(* Logix 5000 project; controller Test vendor 1 type 14 code 92 rev 33.11; software revision 33.03 *)

TASK MainTask (continuous, watchdog 500 ms) : MainProgram

MODULES
   Local : vendor 1 type 14 code 92 (ICP 0, rev 33.11)
      IN : vendor 1 type 7 code 1 (ICP 3, rev 3.2, Input RPI 20 ms)
      O : vendor 1 type 7 code 15 (ICP 2, rev 3.2, Output RPI 20 ms)
      Ethernet : 1756-ENBT (ICP 1, Ethernet 192.168.0.98, rev 6.4)
         IOLM1 : DXM (Ethernet 192.168.0.1, rev 2.22, StandardDataDriven RPI 20 ms)
END_MODULES

TYPE Banner_IOL_Port_v4 :   // UDT that has all of the data items necessary to communicate with a specific Port on a IO-Link Master
STRUCT
   Port_Controlled : INT;   // Each bit represents a port on an IO-Link Master. Set to 1 to tell AOI to control that port.
   Port_Activate : INT;   // Each bit represents a port on an IO-Link Master. When ON that port will process any commands in queue.
   Port_Read : INT;   // Each bit represents a port on an IO-Link Master. Used to determine when device AOI has requested a Read command.
   Port_Write : INT;   // Each bit represents a port on an IO-Link Master. Used to determine when device AOI has requested a Write command.
   Port_RW_Complete : INT;   // Each bit represents a port on an IO-Link Master. Tells device AOI that Read or Write request has been completed.
   Port_Device_Read : INT;
   Data_Transfer : SINT[190];   // Array to transfer data from IO-Master to device AOIs.
END_STRUCT
END_TYPE

TYPE Banner_IOLM_EL_v4 :   // Error Log for Messages to IOLM.
STRUCT
   RW : SINT;   // 0 = Read, 1 = Write, 3 = AOI Failure.
   Port : SINT;   // Port number that generated error.
   Index : INT;   // IO-Link Index for generated error.
END_STRUCT
END_TYPE

TYPE Banner_IOLM_v4 :   // UDT to control IO-Link Masters.
STRUCT
   Message_Source_Data : SINT[190];
   Message_Destination_Data : SINT[190];
   Error_Log : Banner_IOLM_EL_v4[10];
   Error_Write_Retry : BOOL;
   Num_Error_MSGS : DINT;
   IO_Link_Master_Busy : BOOL;   // 0 = While waiting for a command, 1 = Processing command
   AOI_Reset : BOOL;
   Port_Data : Banner_IOL_Port_v4;   // All of the necessary data to work with the various ports of the IO-Link Master.
   Halt_Operation : BOOL;   // When parameter is 1 the AOI is halted as next available time frame.
   AOI_Halted : BOOL;   // AOI is in standby mode until Halt Operation tag is set back to 0.
END_STRUCT
END_TYPE

TYPE Banner_K50Display_Advanced_PD_V2 :   // K50 Pro Display Advanced
STRUCT
   PDI_Output_Area_1 : SINT;   // 0 = Inactive,1 = Active
   PDI_Output_Area_2 : SINT;   // 0 = Inactive,1 = Active
   PDO_Animation : SINT;   // 0 = Off, 1 = Steady, 2 = Flash, 3 = 2 Color Flash, 4 = 50/50, 5 = 50/50 Rotate, 6 = Chase, 7 = Intensity Sweep, 8 = Color Sweep, 9 Sequence, 10 = Wave, 11 = Double Wave, 12 = Steady Area 1, 13 = Steady Area 2, 14 = Alternate Area1 Area 2
   PDO_Direction : SINT;   // 0 = CCW, 1 = CW
   PDO_Pattern : SINT;   // 0 = Flash, 1 = Strobe, 2 = 3 Pulse, 3 = SOS, 4 = Random
   PDO_Speed : SINT;   // 0 = Slow, 1 = Medium, 2 = Fast, 3 = Custom
   PDO_Dyanamic_Sequence : SINT;   // 0 to 255
   PDO_Sequence_Start_Location : SINT;   // 0 = LED1, 1 = LED2, 2 = LED3, 3 = LED4, 4 = LED5, 5 = LED6, 6 = LED7, 7 = LED8
   PDO_Color_1 : SINT;   // 0 = Green, 1 = Red, 2 = Orange, 3 = Amber, 4 = Yellow, 5 = Lime Green, 6 = Spring Green, 7 = Cyan, 8 = Sky Blue, 9 = Blue, 10 = Violet, 11 = Magenta, 12 = Rose, 13 = White, 14 = Custom 1, 15 = Custom 2
   PDO_Color_1_Intensity : SINT;   // 0 = High, 1 = Medium, 2 = Low, 3 = Off, 4 = Custom
   PDO_Color_2 : SINT;   // 0 = Green, 1 = Red, 2 = Orange, 3 = Amber, 4 = Yellow, 5 = Lime Green, 6 = Spring Green, 7 = Cyan, 8 = Sky Blue, 9 = Blue, 10 = Violet, 11 = Magenta, 12 = Rose, 13 = White, 14 = Custom 1, 15 = Custom 2.
   PDO_Color_2_Intensity : SINT;   // 0 = High, 1 = Medium, 2 = Low, 3 = Off, 4 = Custom
   PDO_Number : INT;
   PDO_String : STRING;
END_STRUCT
END_TYPE

TYPE Banner_K50Display_Display_v4 :   // UDT that covers Display Configuration parameters.
STRUCT
   Intensity : SINT;   // 0 = Low, 1 = Medium, 2 = High, 3 = Ultra High
   Orientation : SINT;   // 0 = Standard, 1 = Flipped
   Scroll_Speed : SINT;   // 0 = Off, 1 = Slow, 2 = Medium, 3 = Fast
   Startup_Message : SINT;   // 0 = Off, 1 = Comms Parameter, 2 = Custom
   Startup_String_Delay : DINT;   // 0 to 65535 ms
   Encoding : SINT;   // 0 = ASCII, 1 = Numeric
   Decimal_Type_1 : SINT;   // 0 = Off, 1 = On, 2 = Flash, 3 = Communication, 4 = Power + Communication.
   Decimal_Type_2 : SINT;   // 0 = Off, 1 = On, 2 = Flash, 3 = Communication, 4 = Power + Communication.
   Decimal_Type_3 : SINT;   // 0 = Off, 1 = On, 2 = Flash, 3 = Communication, 4 = Power + Communication.
   Decimal_Type_4 : SINT;   // 0 = Off, 1 = On, 2 = Flash, 3 = Communication, 4 = Power + Communication.
   Startup_String : STRING;
END_STRUCT
END_TYPE

TYPE Banner_K50Display_Four_PD_v2 :   // K50 Pro Display Four State Full Logic
STRUCT
   PDI_State : SINT;   // 0 = State 1, 1 = State 2, 2 = State 3, 3 = State 4
   PDI_State_Area_1 : SINT;   // 0 = Inactive, 1 = Active
   PDI_State_Area_2 : SINT;   // 0 = Inactive, 1 = Active
   PDO_Job_Input : SINT;   // 0 = Off, 1 = On
   PDO_Number : INT;
   PDO_String : STRING;
END_STRUCT
END_TYPE

TYPE Banner_K50Display_LED_v2 :   // LED Control Process Data for a K50 Pro Display.
STRUCT
   PDI_State_Area_1 : SINT;   // 0 = Inactive, 1 = Active.
   PDI_State_Area_2 : SINT;   // 0 = Inactive, 1 = Active.
   LED_1_Color : SINT;   // 0 = Green, 1 = Red, 2 = Orange, 3 = Amber, 4 = Yellow, 5 = Lime Green, 6 = Spring Green, 7 = Cyan, 8 = Sky Blue, 9 = Blue, 10 = Violet, 11 = Magenta, 12 = Rose, 13 = White, 14 = Custom 1, 15 = Custom 2.
   LED_1_Intensity : SINT;   // 0 to 10 (0 to 100%).
   LED_2_Color : SINT;   // 0 = Green, 1 = Red, 2 = Orange, 3 = Amber, 4 = Yellow, 5 = Lime Green, 6 = Spring Green, 7 = Cyan, 8 = Sky Blue, 9 = Blue, 10 = Violet, 11 = Magenta, 12 = Rose, 13 = White, 14 = Custom 1, 15 = Custom 2.
   LED_2_Intensity : SINT;   // 0 to 10 (0 to 100%).
   LED_3_Color : SINT;   // 0 = Green, 1 = Red, 2 = Orange, 3 = Amber, 4 = Yellow, 5 = Lime Green, 6 = Spring Green, 7 = Cyan, 8 = Sky Blue, 9 = Blue, 10 = Violet, 11 = Magenta, 12 = Rose, 13 = White, 14 = Custom 1, 15 = Custom 2.
   LED_3_Intensity : SINT;   // 0 to 10 (0 to 100%).
   LED_4_Color : SINT;   // 0 = Green, 1 = Red, 2 = Orange, 3 = Amber, 4 = Yellow, 5 = Lime Green, 6 = Spring Green, 7 = Cyan, 8 = Sky Blue, 9 = Blue, 10 = Violet, 11 = Magenta, 12 = Rose, 13 = White, 14 = Custom 1, 15 = Custom 2.
   LED_4_Intensity : SINT;   // 0 to 10 (0 to 100%).
   LED_5_Color : SINT;   // 0 = Green, 1 = Red, 2 = Orange, 3 = Amber, 4 = Yellow, 5 = Lime Green, 6 = Spring Green, 7 = Cyan, 8 = Sky Blue, 9 = Blue, 10 = Violet, 11 = Magenta, 12 = Rose, 13 = White, 14 = Custom 1, 15 = Custom 2.
   LED_5_Intensity : SINT;   // 0 to 10 (0 to 100%).
   LED_6_Color : SINT;   // 0 = Green, 1 = Red, 2 = Orange, 3 = Amber, 4 = Yellow, 5 = Lime Green, 6 = Spring Green, 7 = Cyan, 8 = Sky Blue, 9 = Blue, 10 = Violet, 11 = Magenta, 12 = Rose, 13 = White, 14 = Custom 1, 15 = Custom 2.
   LED_6_Intensity : SINT;   // 0 to 10 (0 to 100%).
   LED_7_Color : SINT;   // 0 = Green, 1 = Red, 2 = Orange, 3 = Amber, 4 = Yellow, 5 = Lime Green, 6 = Spring Green, 7 = Cyan, 8 = Sky Blue, 9 = Blue, 10 = Violet, 11 = Magenta, 12 = Rose, 13 = White, 14 = Custom 1, 15 = Custom 2.
   LED_7_Intensity : SINT;   // 0 to 10 (0 to 100%).
   LED_8_Color : SINT;   // 0 = Green, 1 = Red, 2 = Orange, 3 = Amber, 4 = Yellow, 5 = Lime Green, 6 = Spring Green, 7 = Cyan, 8 = Sky Blue, 9 = Blue, 10 = Violet, 11 = Magenta, 12 = Rose, 13 = White, 14 = Custom 1, 15 = Custom 2.
   LED_8_Intensity : SINT;   // 0 to 10 (0 to 100%).
   PDO_Number : INT;
   PDO_String : STRING;
END_STRUCT
END_TYPE

TYPE Banner_K50Display_Multi_PD_v2 :   // K50 Pro Display Multicolor Process Data
STRUCT
   PDI_State : SINT;   // 0 = State 1, 1 = State 2, 2 = State 3, 3 = State 4
   PDI_State_Area_1 : SINT;   // 0 = Inactive, 1 = Active
   PDI_State_Area_2 : SINT;   // 0 = Inactive, 1 = Active
   PDO_State : SINT;   // 0 = State 1, 1 = State 2, 2 = State 3, 3 = State 4
   PDO_Number : INT;
   PDO_String : STRING;
END_STRUCT
END_TYPE

TYPE Banner_K50Display_PDIO_v2 :   // UDT that records the converted prcoess data.
STRUCT
   PD_MultiColor : Banner_K50Display_Multi_PD_v2;   // Only active when Operation Mode set to 0. State tells the light which of the four states it should be in. 0 = State 1, 1 = State 2, 2 = State 3, 3 = State 4.
   PD_FourState : Banner_K50Display_Four_PD_v2;   // Only active when Operation Mode set to 1. Job Input tells the light how it should behave. 0 - Off, 1 = ON
   PD_Advanced : Banner_K50Display_Advanced_PD_V2;   // Only active when Operation Mode set to 2.
   PD_LED : Banner_K50Display_LED_v2;   // Only active when Operation Mode set to 3.
   PDO_DT : SINT[20];
   PDI_DT : SINT[2];
END_STRUCT
END_TYPE

TYPE Banner_K50Display_RD_v4 :   // UDT with all of the Read only parameters for K50 Pro Display.
STRUCT
   Master_Cycle_Time : INT;
   Min_Cycle_Time : INT;
   M_Sequence_Capability : INT;
   IO_Link_Version_ID : INT;
   Process_Data_Input_Length : INT;
   Process_Data_Output_Length : INT;
   Combined_Vendor_ID : DINT;   // IO-Link Vendor ID
   Vendor_ID1 : INT;
   Vendor_ID2 : INT;
   Combined_Device_ID : DINT;   // IO-Link Device ID
   Device_ID1 : INT;
   Device_ID2 : INT;
   Device_ID3 : INT;
   Serial_Number : STRING;
END_STRUCT
END_TYPE

TYPE Banner_K50Display_SP_v4 :   // UDT for K50 Pro Display with the State Parameters structure.
STRUCT
   Type : SINT;   // 0 = Off, 1 = Steady, 2 = Flash, 3 = Two Color Flash, 4 = 50/50, 5 = 50/50 Rotate, 6 = Chase, 7 = Intensity Sweep, 8 = Color Sweep, 9 = Sequence, 10 = Wave, 11 = Double Wave, 12 = Steady Area 1, 13 = Steady Area 2, 14 Alternate Area 1 Area 2
   Direction : SINT;   // 0 = CCW, 1 = CW.
   Pattern : SINT;   // 0 = Flash, 1 = Strobe, 2 = Three Pulse, 3 = SOS, 4 = Random.
   Speed : SINT;   // 0 = Slow, 1 = Medium, 2 = Fast, 3 = Custom.
   Off_Delay_Type : SINT;   // 0 =Leading Edge, 1 = Trailing Edge.
   Off_Delay : DINT;   // 0 to 65535 in ms. Length of time before the device returns to 'touch inactive' state after button is released.
   Static_Sequence : INT;   // 0 to 255. Value describing the LED position of the device.
   Sequence_Start_Location : SINT;   // 0 = LED1, 1 = LED2, 2 = LED3, 3 = LED4, 4 = LED5, 5 = LED6, 6 = LED7, 7 = LED8.
   Color_1 : SINT;   // 0 = Green, 1 = Red, 2 = Orange, 3 = Amber, 4 = Yellow, 5 = Lime Green, 6 = Spring Green, 7 = Cyan, 8 = SKy Blue, 9 = Blue, 10 = Violet, 11 = Magenta, 12 = Rose, 13 = White, 14 Custom 1, 15 = Custom 2.
   Color_1_Intensity : SINT;   // 0 = High, 1 = Medium, 2 = Low, 3 = Off, 4 = Custom.
   Color_2 : SINT;   // 0 = Green, 1 = Red, 2 = Orange, 3 = Amber, 4 = Yellow, 5 = Lime Green, 6 = Spring Green, 7 = Cyan, 8 = SKy Blue, 9 = Blue, 10 = Violet, 11 = Magenta, 12 = Rose, 13 = White, 14 Custom 1, 15 = Custom 2.
   Color_2_Intensity : SINT;   // 0 = High, 1 = Medium, 2 = Low, 3 = Off, 4 = Custom.
END_STRUCT
END_TYPE

TYPE Banner_K50Display_v4 :   // UDT with all of the parameters for K50 Pro Display.
STRUCT
   Initial_Global_Read : BOOL;   // Determines if all of the IO-Link data has been read into the PLC yet
   Command : INT;   // Value placed in here will activate a read or write to a specifc IO-Link Index
   Read : Banner_K50Display_RD_v4;   // All read data
   Write : Banner_K50Display_WD_v4;   // All data that can be written to.
   Archive : Banner_K50Display_WD_v4;   // Archive of the write data.
   Reset : BOOL;
END_STRUCT
END_TYPE

TYPE Banner_K50Display_WD_v4 :   // UDT that stores the Write Data for a K50 Pro Display.
STRUCT
   System_Command : INT;   // See IODD file for list of commands that can be activated via the System Command interface
   Parameter_Access_Lock : SINT;   // Write access to all read/write parameters is block when this bit is ON.
   Data_Storage_Lock : SINT;   // Data storage mechanism is inhibited when bit is ON.
   Local_Parameterization_Lock : SINT;   // Parameteriation via local control elementes is inhibited.
   Local_User_Interface_Lock : SINT;   // Operation of the hmi on the device is disabled.
   Operation_Mode : SINT;   // 0 = Multicolor, 1 = Four State Full Logic, 2 = Advanced, 3 = LED Control, 4 = Demo.
   Custom_Intensity : SINT;   // 0 to 100 %
   Custom_Flash_Rate : INT;   // Range 5 to 200 (.5 to 20 converted rate).
   Restrict_to_Gamut : SINT;   // 0 = Off, 1 = On.
   Touch_Sensitivity : SINT;   // 0 = Low, 1 = Standard, 2 = High.
   Function_1 : SINT;   // 0 = Momentary, 1 = Latched.
   Mute_Enable_1 : SINT;   // 0 = Off, 1 = On.
   Function_2 : SINT;   // 0 = Momentary, 1 = Latched.
   Mute_Enable_2 : SINT;   // 0 = Off, 1 = On.
   On_Delay_1 : DINT;   // 0 to 65535 in ms. Length of time the touch button needs to be pressed to trigger touch active state.
   On_Delay_2 : DINT;   // 0 to 65535 in ms. Length of time the touch button needs to be pressed to trigger touch active state.
   Output_State : SINT;   // 0 = NC, 1 = NO
   Off_Delay_Type_1 : SINT;   // 0 - Leading Edge, 1 = Trailing Edge
   Off_Delay_Type_2 : SINT;   // 0 - Leading Edge, 1 = Trailing Edge
   Off_Delay_1 : DINT;   // Length of time before device returns to touch inactive
   Off_Delay_2 : DINT;   // Length of time before device returns to touch inactive
   State_Parameters : Banner_K50Display_SP_v4[6];   // State Parameters. 1 through 4 will have values.
   CC1_Red : INT;   // 0-255. Custom 1 Red.
   CC1_Green : INT;   // 0-255. Custom 1 Green.
   CC1_Blue : INT;   // 0-255. Custom 1 Blue.
   CC2_Red : INT;   // 0-255. Custom 2 Red.
   CC2_Green : INT;   // 0-255. Custom 2 Green.
   CC2_Blue : INT;   // 0-255. Custom 2 Blue.
   Display_Config : Banner_K50Display_Display_v4;
END_STRUCT
END_TYPE

ADD_ON_INSTRUCTION Banner_DXMR_IOLM_Param_v4   (* revision 4.3, vendor Banner Engineering *)
// AOI that controls a Banner IO-Link Master with Banner devices for parameter data operations.
// Revision note:
// Updated name of AOI.
VAR_IN_OUT
   IOLM : Banner_IOLM_v4; {required}
END_VAR
VAR
   Lock : DINT; {access None}
   Byte_Length : SINT; {access None}
   Current_Port : INT; {access None}   // Current port to communicate with via the IO-Link Master.
   Timer1 : TIMER := (PRE := 500); {access None}
   Error_Index : DINT; {access None}
   Timer2 : TIMER := (PRE := 5000); {access None}
   Temp_Index : INT; {access None}
   ErrCount : DINT; {access None}
   Timer4 : TIMER := (PRE := 2000); {access None}
   Timer5 : TIMER := (PRE := 2000); {access None}
   Timer3 : TIMER := (PRE := 2000); {access None}
   Timer6 : TIMER := (PRE := 3000); {access None}
   Timer7 : TIMER := (PRE := 3000); {access None}
   Timer8 : TIMER := (PRE := 3000); {access None}
END_VAR

ROUTINE Logic   (* ladder *)
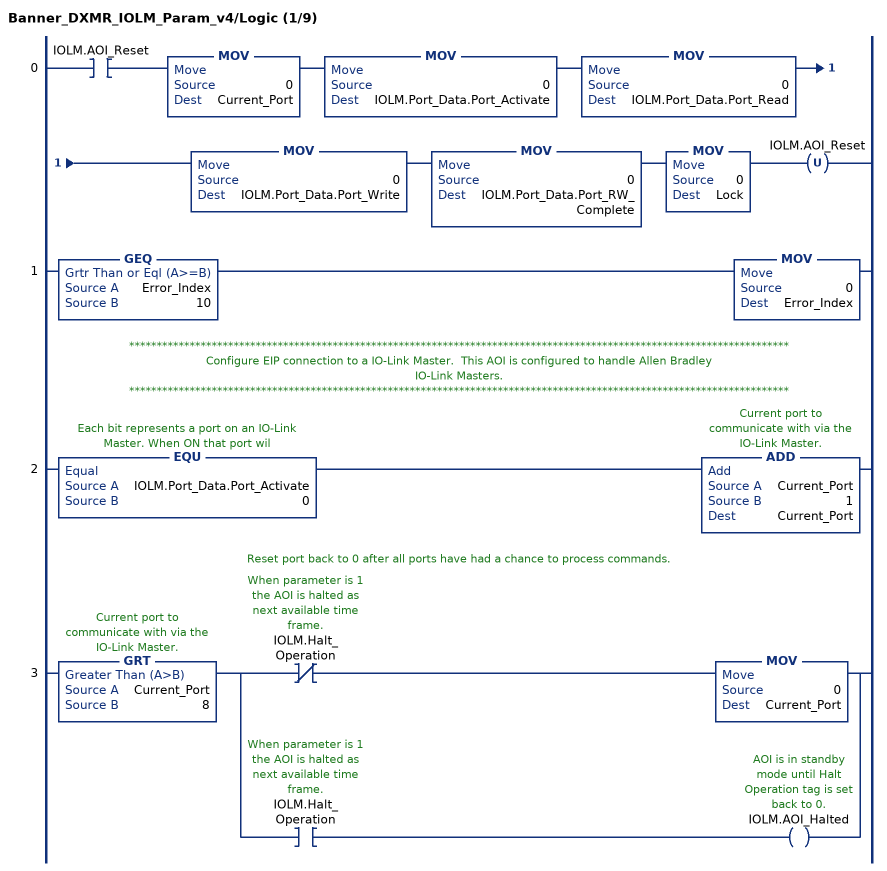
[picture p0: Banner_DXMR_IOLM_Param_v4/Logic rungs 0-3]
   0: XIC(IOLM.AOI_Reset)MOV(0,Current_Port)MOV(0,IOLM.Port_Data.Port_Activate)MOV(0,IOLM.Port_Data.Port_Read)MOV(0,IOLM.Port_Data.Port_Write)MOV(0,IOLM.Port_Data.Port_RW_Complete)MOV(0,Lock)OTU(IOLM.AOI_Reset);
   1: GEQ(Error_Index,10)MOV(0,Error_Index);
   // ************************************************************************************************************************
   // Configure EIP connection to a IO-Link Master.  This AOI is configured to handle Allen Bradley
   // IO-Link Masters.
   // ************************************************************************************************************************
   2: EQU(IOLM.Port_Data.Port_Activate,0)ADD(Current_Port,1,Current_Port);
   // Reset port back to 0 after all ports have had a chance to process commands.
   3: GRT(Current_Port,8)[XIO(IOLM.Halt_Operation) MOV(0,Current_Port) ,XIC(IOLM.Halt_Operation) OTE(IOLM.AOI_Halted) ];
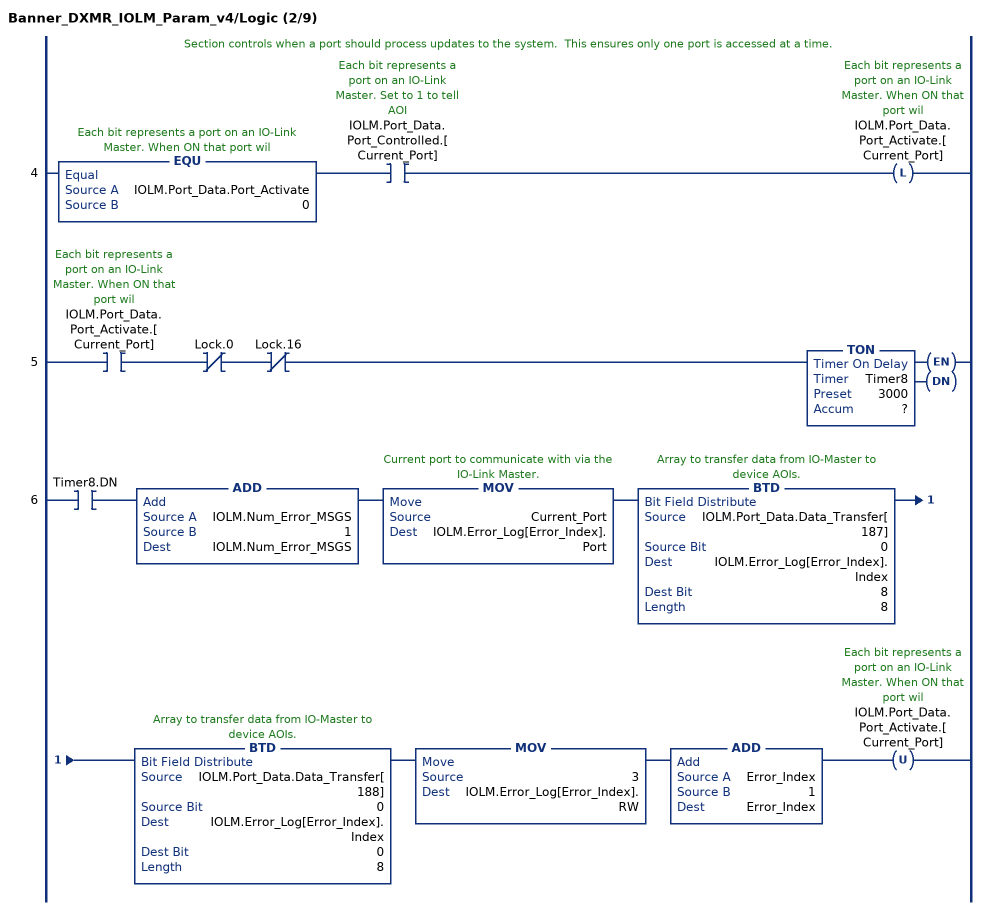
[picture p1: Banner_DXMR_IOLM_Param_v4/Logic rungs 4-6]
   // Section controls when a port should process updates to the system.  This ensures only one port is accessed at a time.
   4: EQU(IOLM.Port_Data.Port_Activate,0)XIC(IOLM.Port_Data.Port_Controlled.[Current_Port])OTL(IOLM.Port_Data.Port_Activate.[Current_Port]);
   5: XIC(IOLM.Port_Data.Port_Activate.[Current_Port])XIO(Lock.0)XIO(Lock.16)TON(Timer8,?,?);
   6: XIC(Timer8.DN)ADD(IOLM.Num_Error_MSGS,1,IOLM.Num_Error_MSGS)MOV(Current_Port,IOLM.Error_Log[Error_Index].Port)BTD(IOLM.Port_Data.Data_Transfer[187],0,IOLM.Error_Log[Error_Index].Index,8,8)BTD(IOLM.Port_Data.Data_Transfer[188],0,IOLM.Error_Log[Error_Index].Index,0,8)MOV(3,IOLM.Error_Log[Error_Index].RW)ADD(Error_Index,1,Error_Index)OTU(IOLM.Port_Data.Port_Activate.[Current_Port]);
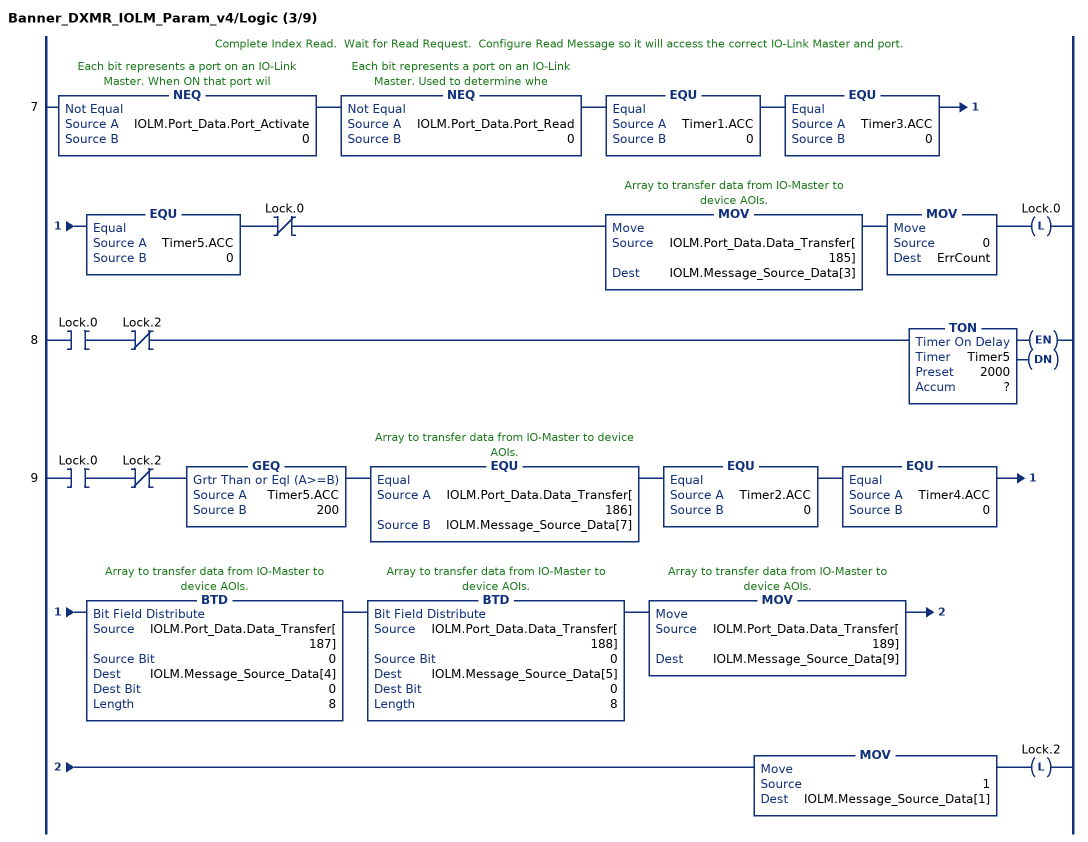
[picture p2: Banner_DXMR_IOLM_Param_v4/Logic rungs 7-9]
   // Complete Index Read.  Wait for Read Request.  Configure Read Message so it will access the correct IO-Link Master and port.
   7: NEQ(IOLM.Port_Data.Port_Activate,0)NEQ(IOLM.Port_Data.Port_Read,0)EQU(Timer1.ACC,0)EQU(Timer3.ACC,0)EQU(Timer5.ACC,0)XIO(Lock.0)MOV(IOLM.Port_Data.Data_Transfer[185],IOLM.Message_Source_Data[3])MOV(0,ErrCount)OTL(Lock.0);
   8: XIC(Lock.0)XIO(Lock.2)TON(Timer5,?,?);
   9: XIC(Lock.0)XIO(Lock.2)GEQ(Timer5.ACC,200)EQU(IOLM.Port_Data.Data_Transfer[186],IOLM.Message_Source_Data[7])EQU(Timer2.ACC,0)EQU(Timer4.ACC,0)BTD(IOLM.Port_Data.Data_Transfer[187],0,IOLM.Message_Source_Data[4],0,8)BTD(IOLM.Port_Data.Data_Transfer[188],0,IOLM.Message_Source_Data[5],0,8)MOV(IOLM.Port_Data.Data_Transfer[189],IOLM.Message_Source_Data[9])MOV(1,IOLM.Message_Source_Data[1])OTL(Lock.2);
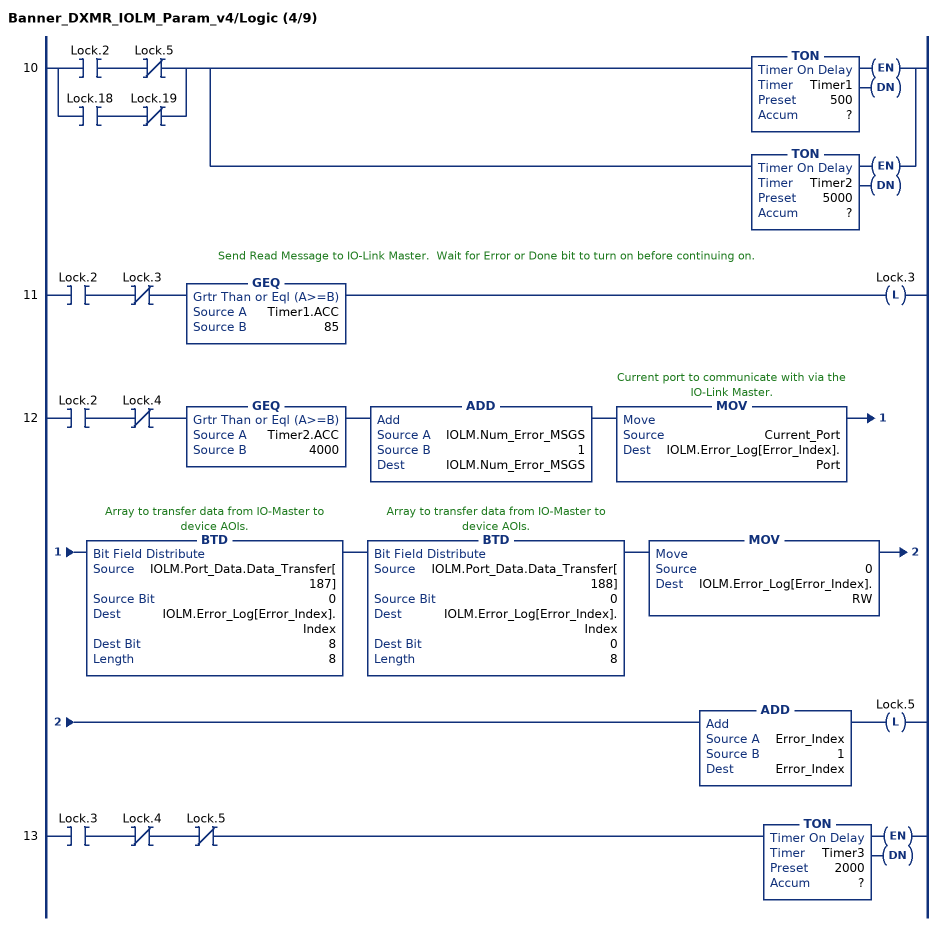
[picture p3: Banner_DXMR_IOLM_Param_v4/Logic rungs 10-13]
   10: [XIC(Lock.2) XIO(Lock.5) ,XIC(Lock.18) XIO(Lock.19) ][TON(Timer1,?,?) ,TON(Timer2,?,?) ];
   // Send Read Message to IO-Link Master.  Wait for Error or Done bit to turn on before continuing on.
   11: XIC(Lock.2)XIO(Lock.3)GEQ(Timer1.ACC,85)OTL(Lock.3);
   12: XIC(Lock.2)XIO(Lock.4)GEQ(Timer2.ACC,4000)ADD(IOLM.Num_Error_MSGS,1,IOLM.Num_Error_MSGS)MOV(Current_Port,IOLM.Error_Log[Error_Index].Port)BTD(IOLM.Port_Data.Data_Transfer[187],0,IOLM.Error_Log[Error_Index].Index,8,8)BTD(IOLM.Port_Data.Data_Transfer[188],0,IOLM.Error_Log[Error_Index].Index,0,8)MOV(0,IOLM.Error_Log[Error_Index].RW)ADD(Error_Index,1,Error_Index)OTL(Lock.5);
   13: XIC(Lock.3)XIO(Lock.4)XIO(Lock.5)TON(Timer3,?,?);
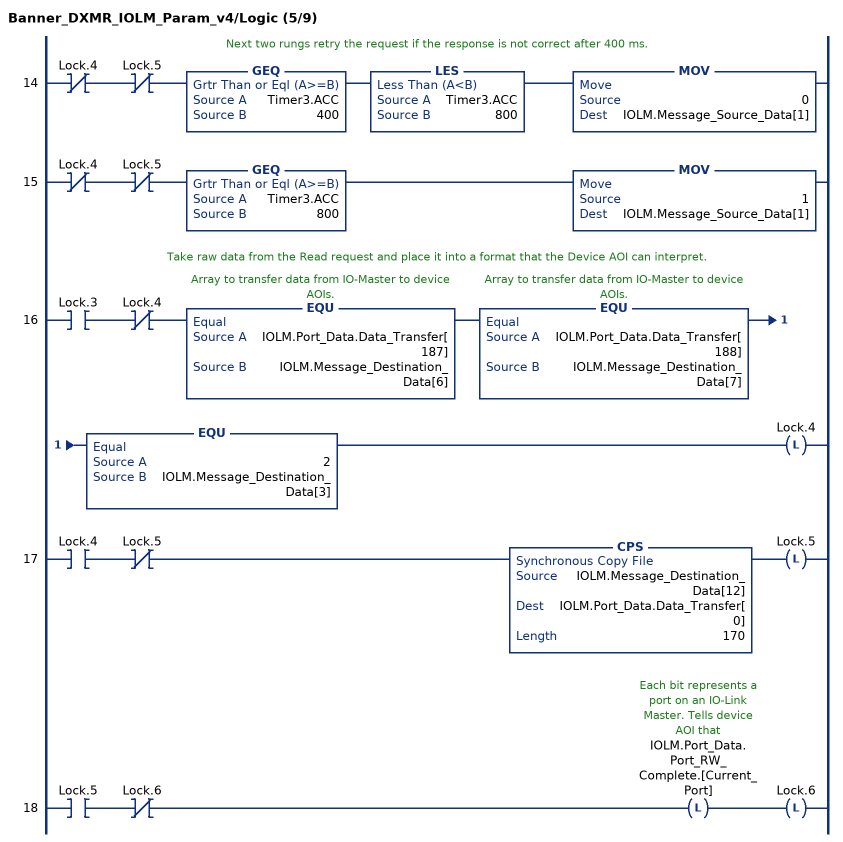
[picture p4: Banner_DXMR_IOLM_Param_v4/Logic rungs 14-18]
   // Next two rungs retry the request if the response is not correct after 400 ms.
   14: XIO(Lock.4)XIO(Lock.5)GEQ(Timer3.ACC,400)LES(Timer3.ACC,800)MOV(0,IOLM.Message_Source_Data[1]);
   15: XIO(Lock.4)XIO(Lock.5)GEQ(Timer3.ACC,800)MOV(1,IOLM.Message_Source_Data[1]);
   // Take raw data from the Read request and place it into a format that the Device AOI can interpret.
   16: XIC(Lock.3)XIO(Lock.4)EQU(IOLM.Port_Data.Data_Transfer[187],IOLM.Message_Destination_Data[6])EQU(IOLM.Port_Data.Data_Transfer[188],IOLM.Message_Destination_Data[7])EQU(2,IOLM.Message_Destination_Data[3])OTL(Lock.4);
   17: XIC(Lock.4)XIO(Lock.5)CPS(IOLM.Message_Destination_Data[12],IOLM.Port_Data.Data_Transfer[0],170)OTL(Lock.5);
   18: XIC(Lock.5)XIO(Lock.6)OTL(IOLM.Port_Data.Port_RW_Complete.[Current_Port])OTL(Lock.6);
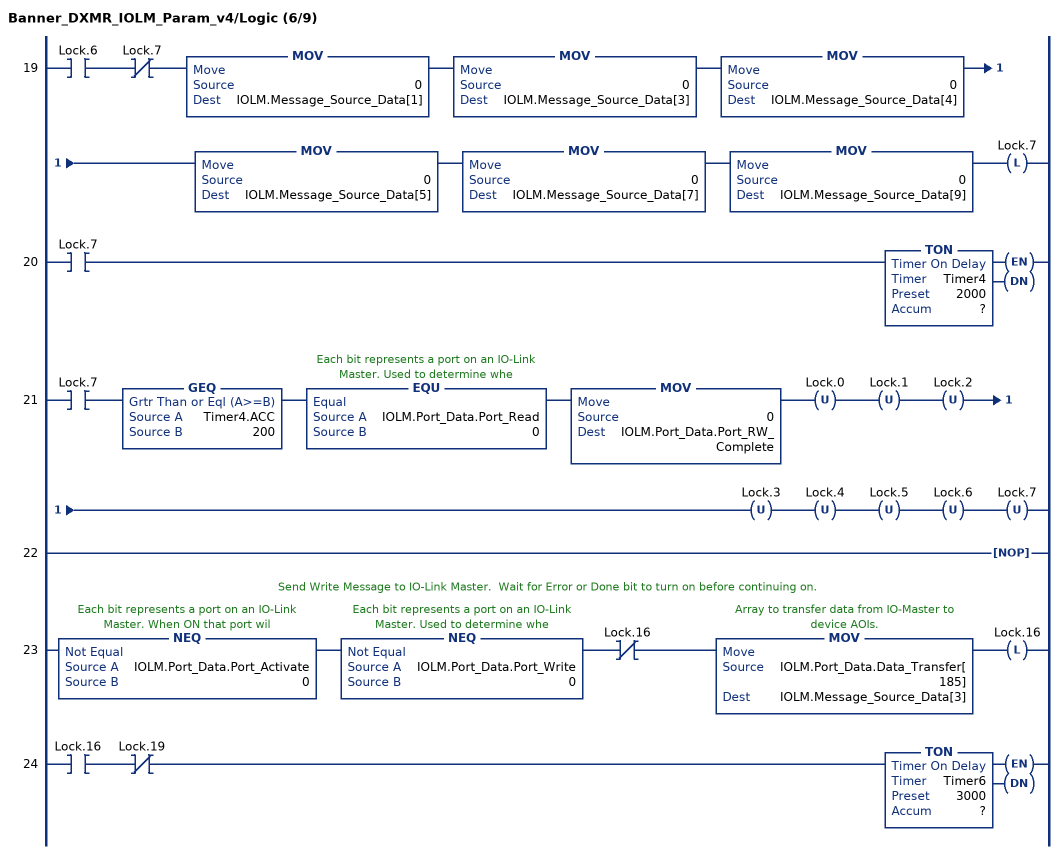
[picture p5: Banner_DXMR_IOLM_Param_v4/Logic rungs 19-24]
   19: XIC(Lock.6)XIO(Lock.7)MOV(0,IOLM.Message_Source_Data[1])MOV(0,IOLM.Message_Source_Data[3])MOV(0,IOLM.Message_Source_Data[4])MOV(0,IOLM.Message_Source_Data[5])MOV(0,IOLM.Message_Source_Data[7])MOV(0,IOLM.Message_Source_Data[9])OTL(Lock.7);
   20: XIC(Lock.7)TON(Timer4,?,?);
   21: XIC(Lock.7)GEQ(Timer4.ACC,200)EQU(IOLM.Port_Data.Port_Read,0)MOV(0,IOLM.Port_Data.Port_RW_Complete)OTU(Lock.0)OTU(Lock.1)OTU(Lock.2)OTU(Lock.3)OTU(Lock.4)OTU(Lock.5)OTU(Lock.6)OTU(Lock.7);
   22: NOP();
   // Send Write Message to IO-Link Master.  Wait for Error or Done bit to turn on before continuing on.
   23: NEQ(IOLM.Port_Data.Port_Activate,0)NEQ(IOLM.Port_Data.Port_Write,0)XIO(Lock.16)MOV(IOLM.Port_Data.Data_Transfer[185],IOLM.Message_Source_Data[3])OTL(Lock.16);
   24: XIC(Lock.16)XIO(Lock.19)TON(Timer6,?,?);
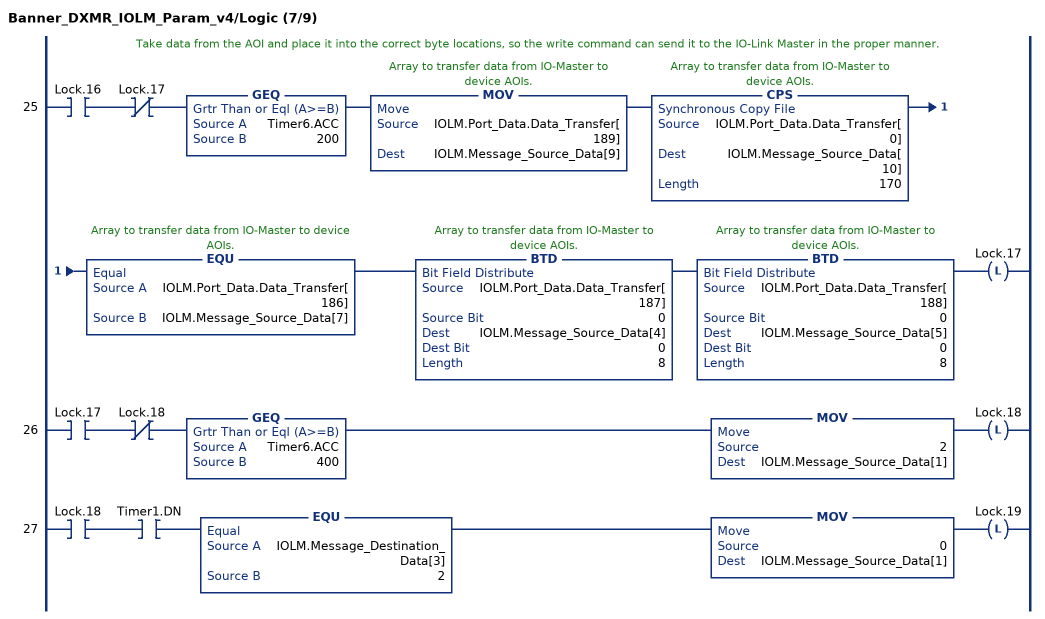
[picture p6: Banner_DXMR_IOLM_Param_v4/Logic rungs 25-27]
   // Take data from the AOI and place it into the correct byte locations, so the write command can send it to the IO-Link Master in the proper manner.
   25: XIC(Lock.16)XIO(Lock.17)GEQ(Timer6.ACC,200)MOV(IOLM.Port_Data.Data_Transfer[189],IOLM.Message_Source_Data[9])CPS(IOLM.Port_Data.Data_Transfer[0],IOLM.Message_Source_Data[10],170)EQU(IOLM.Port_Data.Data_Transfer[186],IOLM.Message_Source_Data[7])BTD(IOLM.Port_Data.Data_Transfer[187],0,IOLM.Message_Source_Data[4],0,8)BTD(IOLM.Port_Data.Data_Transfer[188],0,IOLM.Message_Source_Data[5],0,8)OTL(Lock.17);
   26: XIC(Lock.17)XIO(Lock.18)GEQ(Timer6.ACC,400)MOV(2,IOLM.Message_Source_Data[1])OTL(Lock.18);
   27: XIC(Lock.18)XIC(Timer1.DN)EQU(IOLM.Message_Destination_Data[3],2)MOV(0,IOLM.Message_Source_Data[1])OTL(Lock.19);
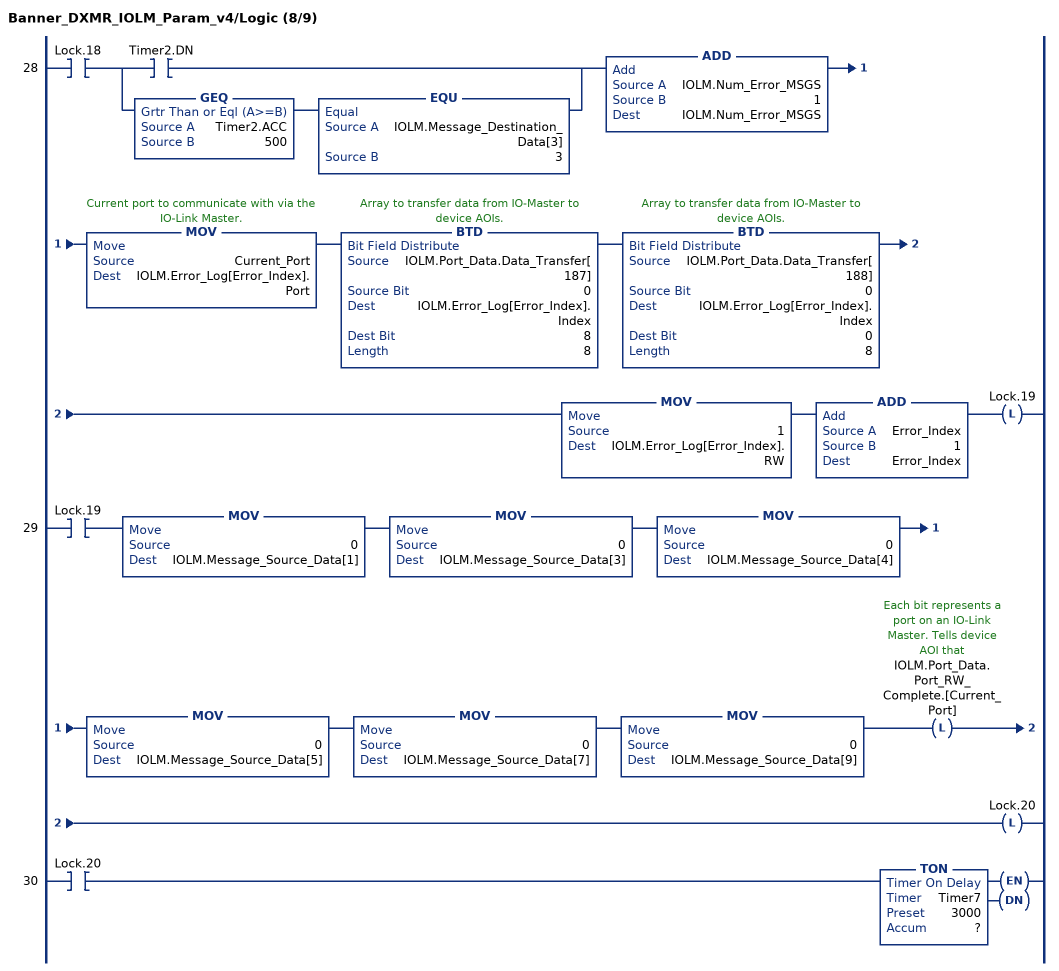
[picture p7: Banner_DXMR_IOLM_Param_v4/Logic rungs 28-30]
   28: XIC(Lock.18)[XIC(Timer2.DN) ,GEQ(Timer2.ACC,500) EQU(IOLM.Message_Destination_Data[3],3) ]ADD(IOLM.Num_Error_MSGS,1,IOLM.Num_Error_MSGS)MOV(Current_Port,IOLM.Error_Log[Error_Index].Port)BTD(IOLM.Port_Data.Data_Transfer[187],0,IOLM.Error_Log[Error_Index].Index,8,8)BTD(IOLM.Port_Data.Data_Transfer[188],0,IOLM.Error_Log[Error_Index].Index,0,8)MOV(1,IOLM.Error_Log[Error_Index].RW)ADD(Error_Index,1,Error_Index)OTL(Lock.19);
   29: XIC(Lock.19)MOV(0,IOLM.Message_Source_Data[1])MOV(0,IOLM.Message_Source_Data[3])MOV(0,IOLM.Message_Source_Data[4])MOV(0,IOLM.Message_Source_Data[5])MOV(0,IOLM.Message_Source_Data[7])MOV(0,IOLM.Message_Source_Data[9])OTL(IOLM.Port_Data.Port_RW_Complete.[Current_Port])OTL(Lock.20);
   30: XIC(Lock.20)TON(Timer7,?,?);
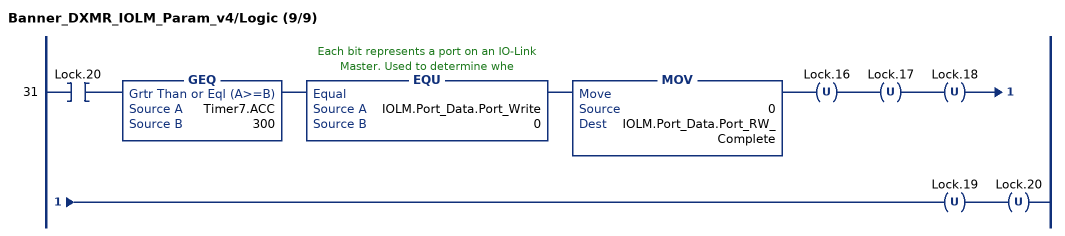
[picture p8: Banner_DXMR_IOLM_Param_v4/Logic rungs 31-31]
   31: XIC(Lock.20)GEQ(Timer7.ACC,300)EQU(IOLM.Port_Data.Port_Write,0)MOV(0,IOLM.Port_Data.Port_RW_Complete)OTU(Lock.16)OTU(Lock.17)OTU(Lock.18)OTU(Lock.19)OTU(Lock.20);
END_ROUTINE
END_ADD_ON_INSTRUCTION

ADD_ON_INSTRUCTION Banner_K50Display_Param_v4   (* revision 4.2, vendor Banner Engineering *)
// AOI to read and write parameter data to an IO-Link K50 Pro Display.
// Revision note:
// Resolved transfer array index issue.
VAR_IN_OUT
   K50 : Banner_K50Display_v4; {required}
   Port_Data : Banner_IOL_Port_v4; {required}
END_VAR
VAR_INPUT
   Port : DINT; {required}
END_VAR
VAR
   Local_Control : DINT; {access None}
   Global_Read_Command_Value : INT; {access None}
   Global_Write_Command_Value : INT; {access None}
   Command_Being_Processed : BOOL; {access None}
   Update_Archive : BOOL; {access None}
   Index_Write_Control : DINT; {access None}
   Index_Write_Inprocess : INT; {access None}
   Temp_Excess_Gain : DINT[2]; {access None}
   Inprocess_Index : DINT; {access None}
   SP_Index : DINT; {access None}   // State Parameters Index
   SP_Write_Index : DINT; {access None}
   SP_R_Index : DINT; {access None}
   SP_W_Index : DINT; {access None}
END_VAR

ROUTINE Logic   (* ladder *)
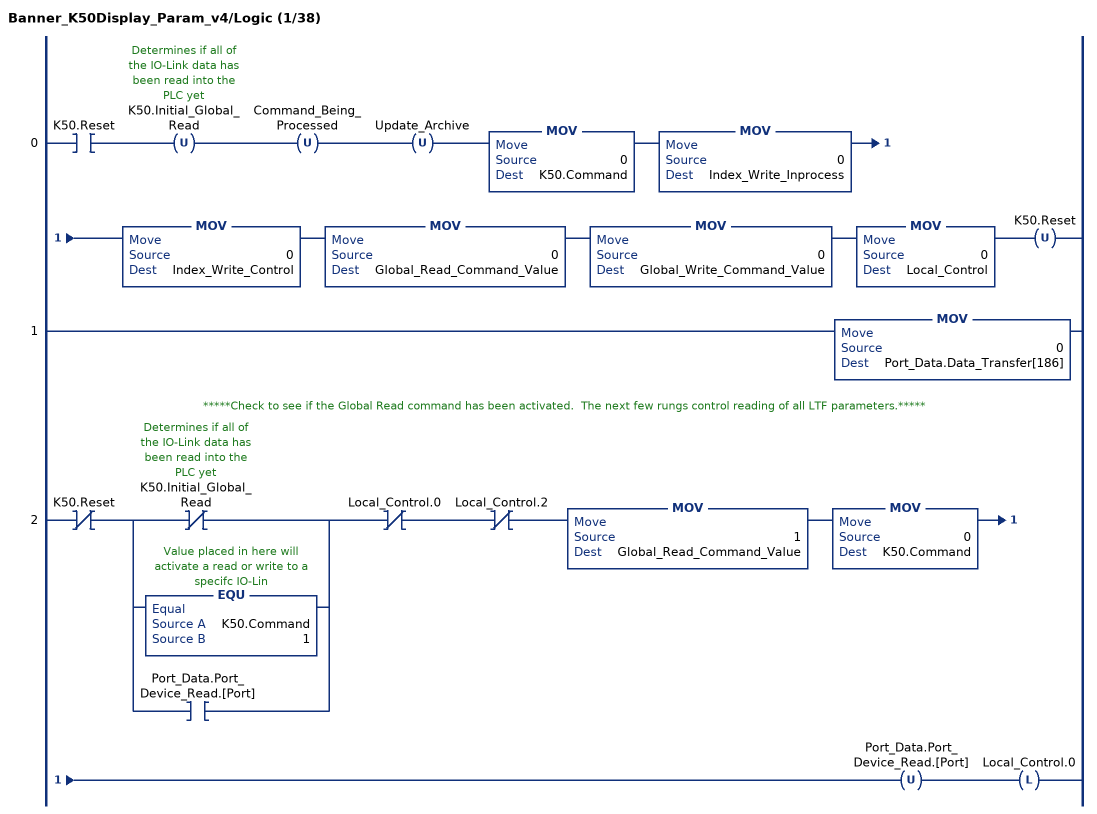
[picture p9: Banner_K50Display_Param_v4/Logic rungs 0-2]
   0: XIC(K50.Reset)OTU(K50.Initial_Global_Read)OTU(Command_Being_Processed)OTU(Update_Archive)MOV(0,K50.Command)MOV(0,Index_Write_Inprocess)MOV(0,Index_Write_Control)MOV(0,Global_Read_Command_Value)MOV(0,Global_Write_Command_Value)MOV(0,Local_Control)OTU(K50.Reset);
   1: MOV(0,Port_Data.Data_Transfer[186]);
   // *****Check to see if the Global Read command has been activated.  The next few rungs control reading of all LTF parameters.*****
   2: XIO(K50.Reset)[XIO(K50.Initial_Global_Read) ,EQU(K50.Command,1) ,XIC(Port_Data.Port_Device_Read.[Port]) ]XIO(Local_Control.0)XIO(Local_Control.2)MOV(1,Global_Read_Command_Value)MOV(0,K50.Command)OTU(Port_Data.Port_Device_Read.[Port])OTL(Local_Control.0);
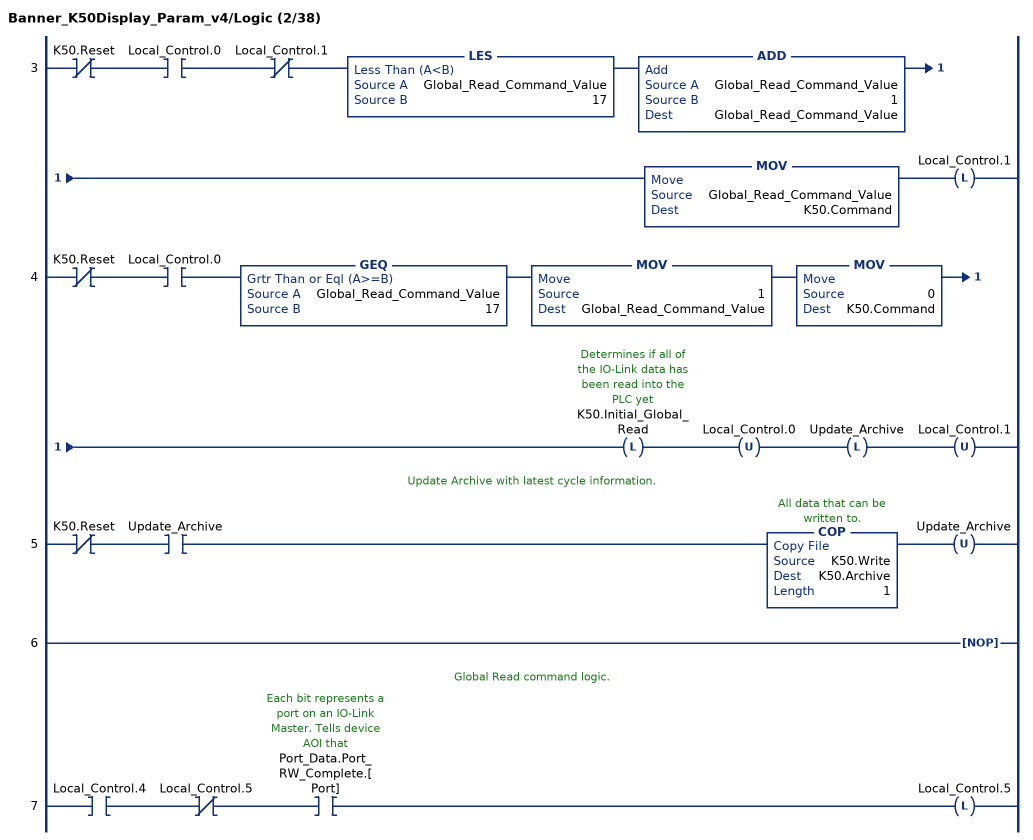
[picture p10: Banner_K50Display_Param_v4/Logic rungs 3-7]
   3: XIO(K50.Reset)XIC(Local_Control.0)XIO(Local_Control.1)LES(Global_Read_Command_Value,17)ADD(Global_Read_Command_Value,1,Global_Read_Command_Value)MOV(Global_Read_Command_Value,K50.Command)OTL(Local_Control.1);
   4: XIO(K50.Reset)XIC(Local_Control.0)GEQ(Global_Read_Command_Value,17)MOV(1,Global_Read_Command_Value)MOV(0,K50.Command)OTL(K50.Initial_Global_Read)OTU(Local_Control.0)OTL(Update_Archive)OTU(Local_Control.1);
   // Update Archive with latest cycle information.
   5: XIO(K50.Reset)XIC(Update_Archive)COP(K50.Write,K50.Archive,1)OTU(Update_Archive);
   6: NOP();
   // Global Read command logic.
   7: XIC(Local_Control.4)XIO(Local_Control.5)XIC(Port_Data.Port_RW_Complete.[Port])OTL(Local_Control.5);
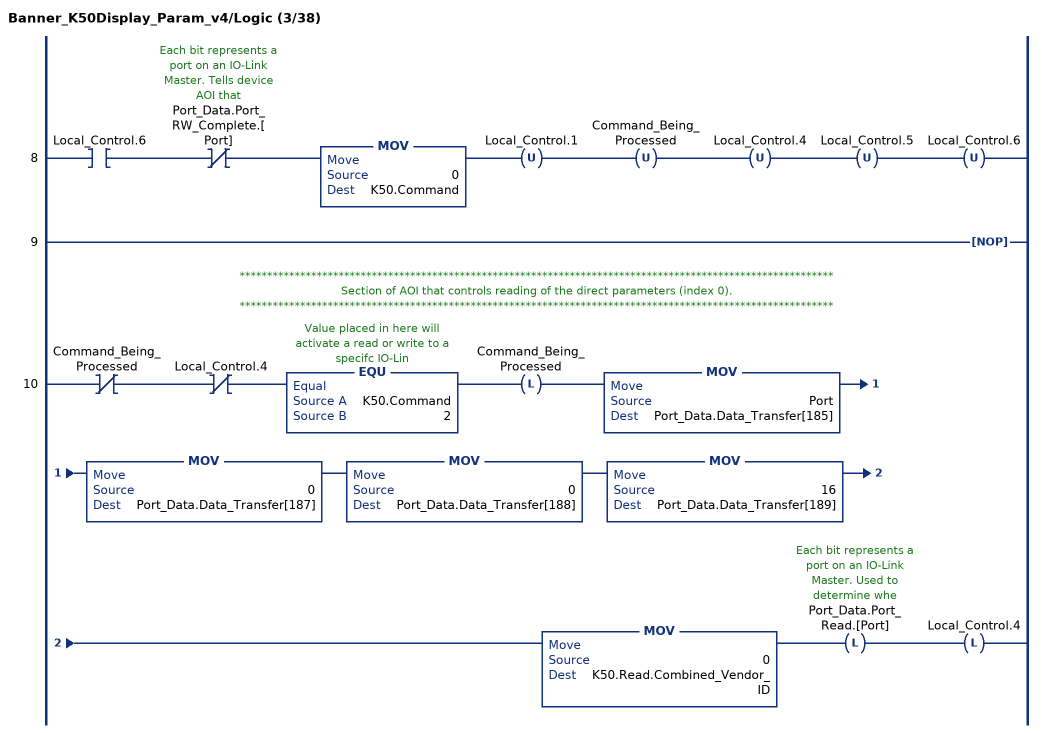
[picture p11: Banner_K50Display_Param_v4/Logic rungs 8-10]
   8: XIC(Local_Control.6)XIO(Port_Data.Port_RW_Complete.[Port])MOV(0,K50.Command)OTU(Local_Control.1)OTU(Command_Being_Processed)OTU(Local_Control.4)OTU(Local_Control.5)OTU(Local_Control.6);
   9: NOP();
   // ************************************************************************************************************
   // Section of AOI that controls reading of the direct parameters (index 0).
   // ************************************************************************************************************
   10: XIO(Command_Being_Processed)XIO(Local_Control.4)EQU(K50.Command,2)OTL(Command_Being_Processed)MOV(Port,Port_Data.Data_Transfer[185])MOV(0,Port_Data.Data_Transfer[187])MOV(0,Port_Data.Data_Transfer[188])MOV(16,Port_Data.Data_Transfer[189])MOV(0,K50.Read.Combined_Vendor_ID)OTL(Port_Data.Port_Read.[Port])OTL(Local_Control.4);
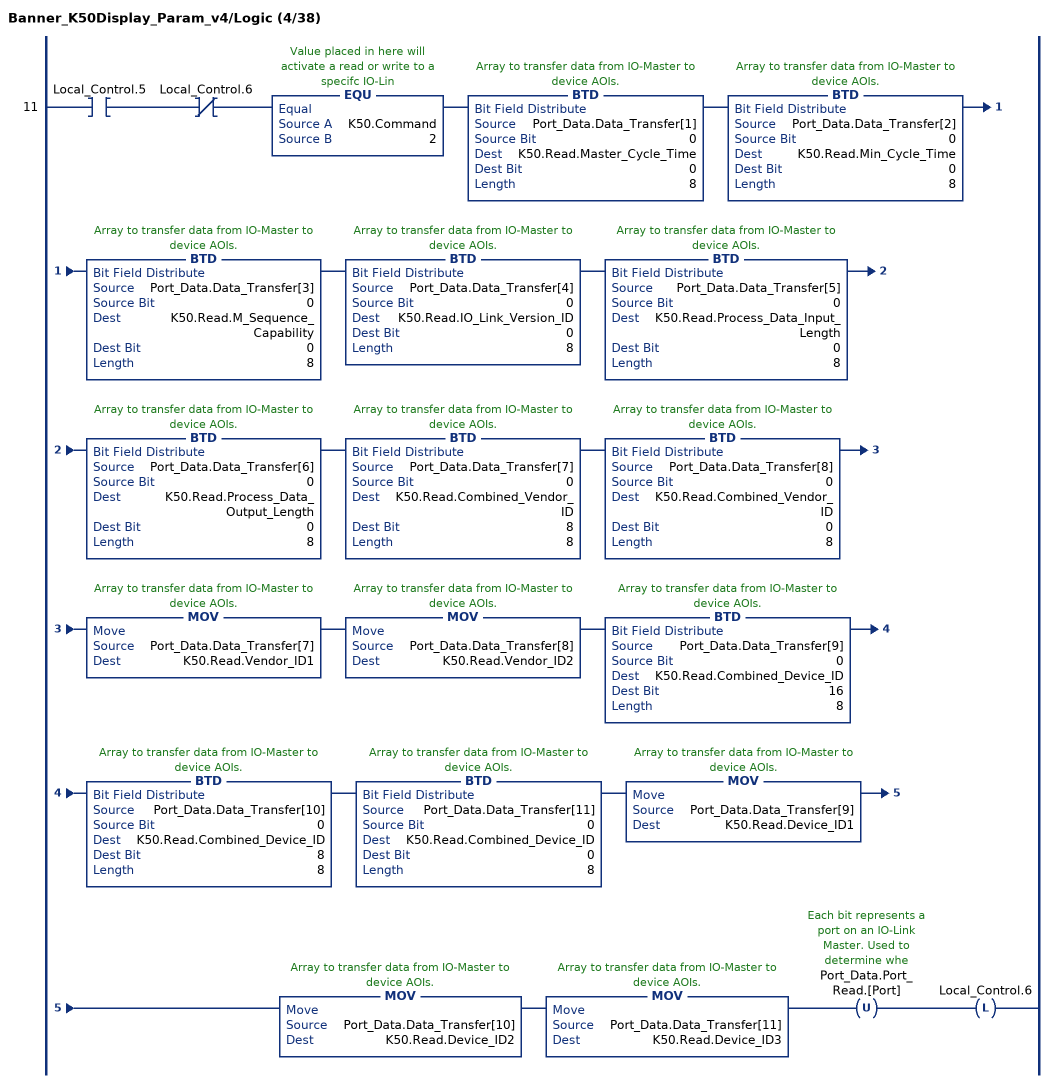
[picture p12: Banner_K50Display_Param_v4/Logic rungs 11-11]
   11: XIC(Local_Control.5)XIO(Local_Control.6)EQU(K50.Command,2)BTD(Port_Data.Data_Transfer[1],0,K50.Read.Master_Cycle_Time,0,8)BTD(Port_Data.Data_Transfer[2],0,K50.Read.Min_Cycle_Time,0,8)BTD(Port_Data.Data_Transfer[3],0,K50.Read.M_Sequence_Capability,0,8)BTD(Port_Data.Data_Transfer[4],0,K50.Read.IO_Link_Version_ID,0,8)BTD(Port_Data.Data_Transfer[5],0,K50.Read.Process_Data_Input_Length,0,8)BTD(Port_Data.Data_Transfer[6],0,K50.Read.Process_Data_Output_Length,0,8)BTD(Port_Data.Data_Transfer[7],0,K50.Read.Combined_Vendor_ID,8,8)BTD(Port_Data.Data_Transfer[8],0,K50.Read.Combined_Vendor_ID,0,8)MOV(Port_Data.Data_Transfer[7],K50.Read.Vendor_ID1)MOV(Port_Data.Data_Transfer[8],K50.Read.Vendor_ID2)BTD(Port_Data.Data_Transfer[9],0,K50.Read.Combined_Device_ID,16,8)BTD(Port_Data.Data_Transfer[10],0,K50.Read.Combined_Device_ID,8,8)BTD(Port_Data.Data_Transfer[11],0,K50.Read.Combined_Device_ID,0,8)MOV(Port_Data.Data_Transfer[9],K50.Read.Device_ID1)MOV(Port_Data.Data_Transfer[10],K50.Read.Device_ID2)MOV(Port_Data.Data_Transfer[11],K50.Read.Device_ID3)OTU(Port_Data.Port_Read.[Port])OTL(Local_Control.6);
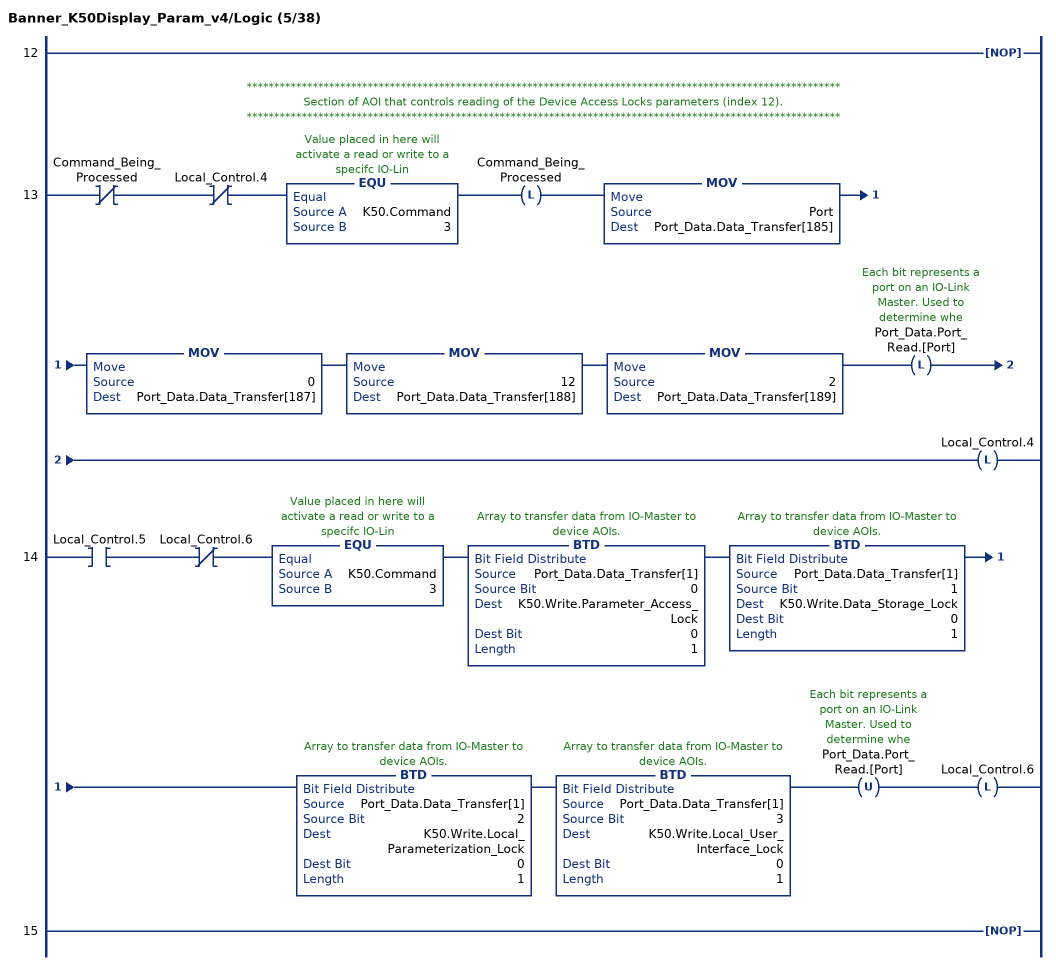
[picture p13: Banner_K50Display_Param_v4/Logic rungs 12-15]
   12: NOP();
   // ************************************************************************************************************
   // Section of AOI that controls reading of the Device Access Locks parameters (index 12).
   // ************************************************************************************************************
   13: XIO(Command_Being_Processed)XIO(Local_Control.4)EQU(K50.Command,3)OTL(Command_Being_Processed)MOV(Port,Port_Data.Data_Transfer[185])MOV(0,Port_Data.Data_Transfer[187])MOV(12,Port_Data.Data_Transfer[188])MOV(2,Port_Data.Data_Transfer[189])OTL(Port_Data.Port_Read.[Port])OTL(Local_Control.4);
   14: XIC(Local_Control.5)XIO(Local_Control.6)EQU(K50.Command,3)BTD(Port_Data.Data_Transfer[1],0,K50.Write.Parameter_Access_Lock,0,1)BTD(Port_Data.Data_Transfer[1],1,K50.Write.Data_Storage_Lock,0,1)BTD(Port_Data.Data_Transfer[1],2,K50.Write.Local_Parameterization_Lock,0,1)BTD(Port_Data.Data_Transfer[1],3,K50.Write.Local_User_Interface_Lock,0,1)OTU(Port_Data.Port_Read.[Port])OTL(Local_Control.6);
   15: NOP();
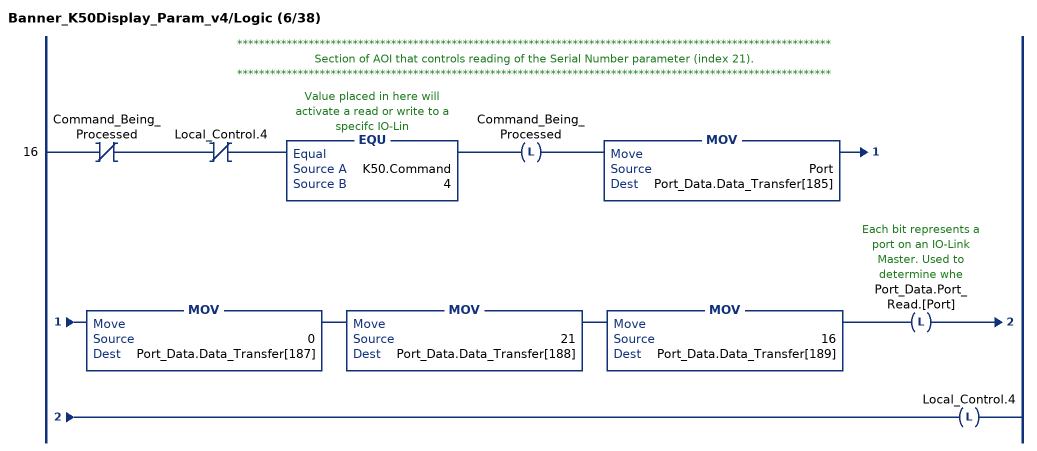
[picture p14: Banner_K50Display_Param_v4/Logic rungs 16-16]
   // ************************************************************************************************************
   // Section of AOI that controls reading of the Serial Number parameter (index 21).
   // ************************************************************************************************************
   16: XIO(Command_Being_Processed)XIO(Local_Control.4)EQU(K50.Command,4)OTL(Command_Being_Processed)MOV(Port,Port_Data.Data_Transfer[185])MOV(0,Port_Data.Data_Transfer[187])MOV(21,Port_Data.Data_Transfer[188])MOV(16,Port_Data.Data_Transfer[189])OTL(Port_Data.Port_Read.[Port])OTL(Local_Control.4);
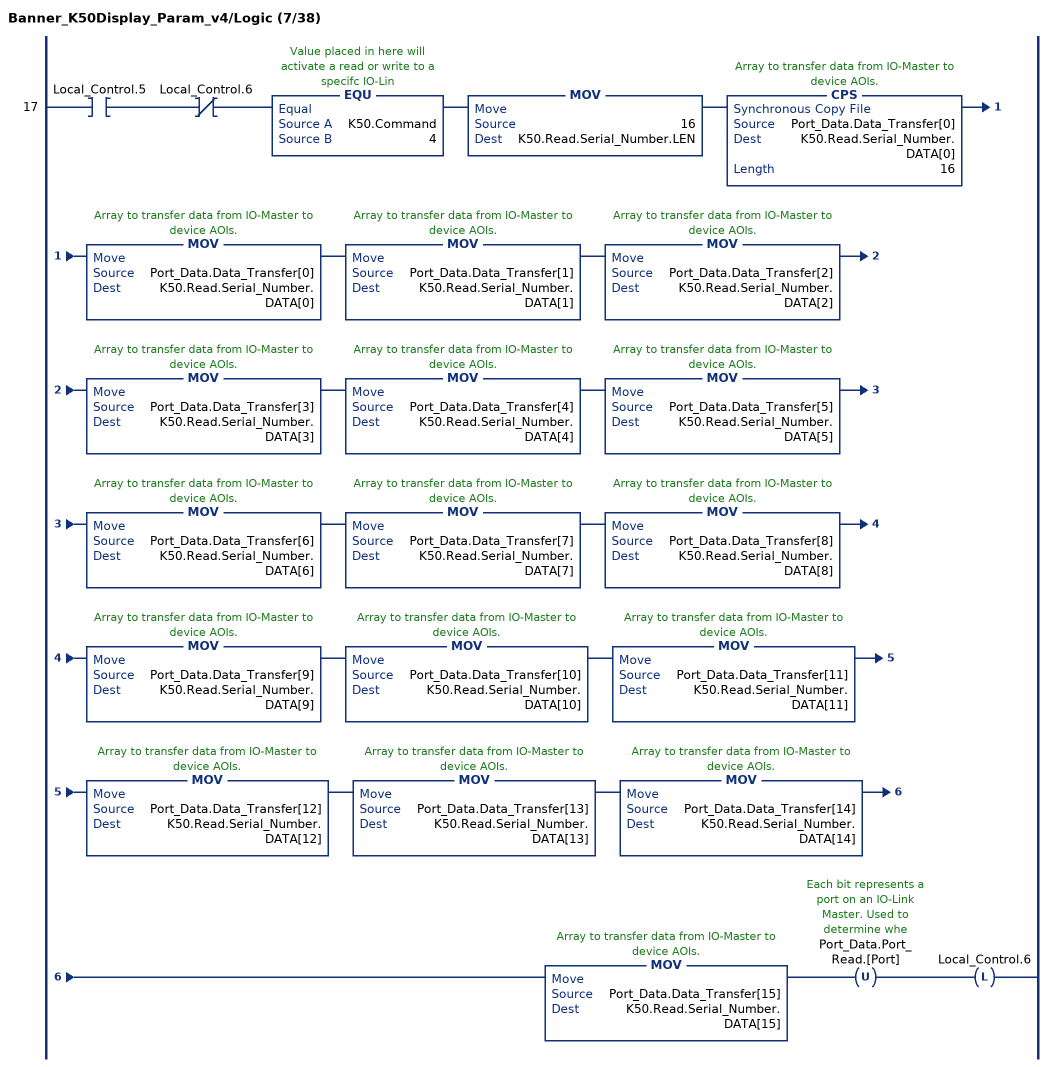
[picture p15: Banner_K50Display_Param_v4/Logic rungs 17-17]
   17: XIC(Local_Control.5)XIO(Local_Control.6)EQU(K50.Command,4)MOV(16,K50.Read.Serial_Number.LEN)CPS(Port_Data.Data_Transfer[0],K50.Read.Serial_Number.DATA[0],16)MOV(Port_Data.Data_Transfer[0],K50.Read.Serial_Number.DATA[0])MOV(Port_Data.Data_Transfer[1],K50.Read.Serial_Number.DATA[1])MOV(Port_Data.Data_Transfer[2],K50.Read.Serial_Number.DATA[2])MOV(Port_Data.Data_Transfer[3],K50.Read.Serial_Number.DATA[3])MOV(Port_Data.Data_Transfer[4],K50.Read.Serial_Number.DATA[4])MOV(Port_Data.Data_Transfer[5],K50.Read.Serial_Number.DATA[5])MOV(Port_Data.Data_Transfer[6],K50.Read.Serial_Number.DATA[6])MOV(Port_Data.Data_Transfer[7],K50.Read.Serial_Number.DATA[7])MOV(Port_Data.Data_Transfer[8],K50.Read.Serial_Number.DATA[8])MOV(Port_Data.Data_Transfer[9],K50.Read.Serial_Number.DATA[9])MOV(Port_Data.Data_Transfer[10],K50.Read.Serial_Number.DATA[10])MOV(Port_Data.Data_Transfer[11],K50.Read.Serial_Number.DATA[11])MOV(Port_Data.Data_Transfer[12],K50.Read.Serial_Number.DATA[12])MOV(Port_Data.Data_Transfer[13],K50.Read.Serial_Number.DATA[13])MOV(Port_Data.Data_Transfer[14],K50.Read.Serial_Number.DATA[14])MOV(Port_Data.Data_Transfer[15],K50.Read.Serial_Number.DATA[15])OTU(Port_Data.Port_Read.[Port])OTL(Local_Control.6);
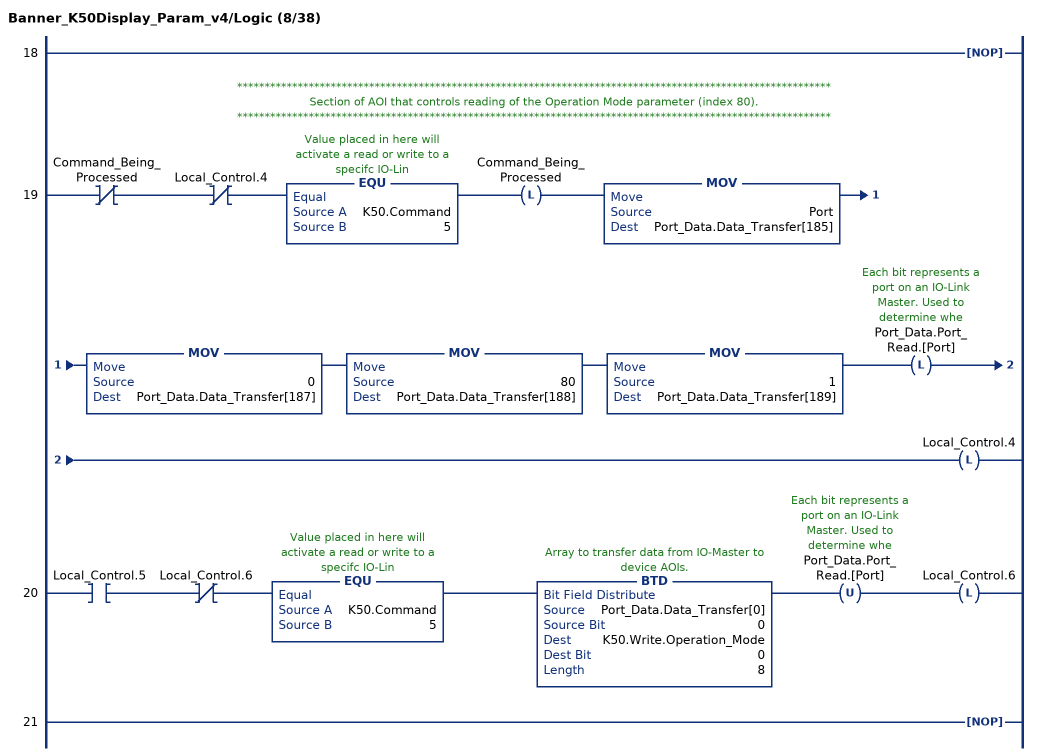
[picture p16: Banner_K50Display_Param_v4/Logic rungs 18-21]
   18: NOP();
   // ************************************************************************************************************
   // Section of AOI that controls reading of the Operation Mode parameter (index 80).
   // ************************************************************************************************************
   19: XIO(Command_Being_Processed)XIO(Local_Control.4)EQU(K50.Command,5)OTL(Command_Being_Processed)MOV(Port,Port_Data.Data_Transfer[185])MOV(0,Port_Data.Data_Transfer[187])MOV(80,Port_Data.Data_Transfer[188])MOV(1,Port_Data.Data_Transfer[189])OTL(Port_Data.Port_Read.[Port])OTL(Local_Control.4);
   20: XIC(Local_Control.5)XIO(Local_Control.6)EQU(K50.Command,5)BTD(Port_Data.Data_Transfer[0],0,K50.Write.Operation_Mode,0,8)OTU(Port_Data.Port_Read.[Port])OTL(Local_Control.6);
   21: NOP();
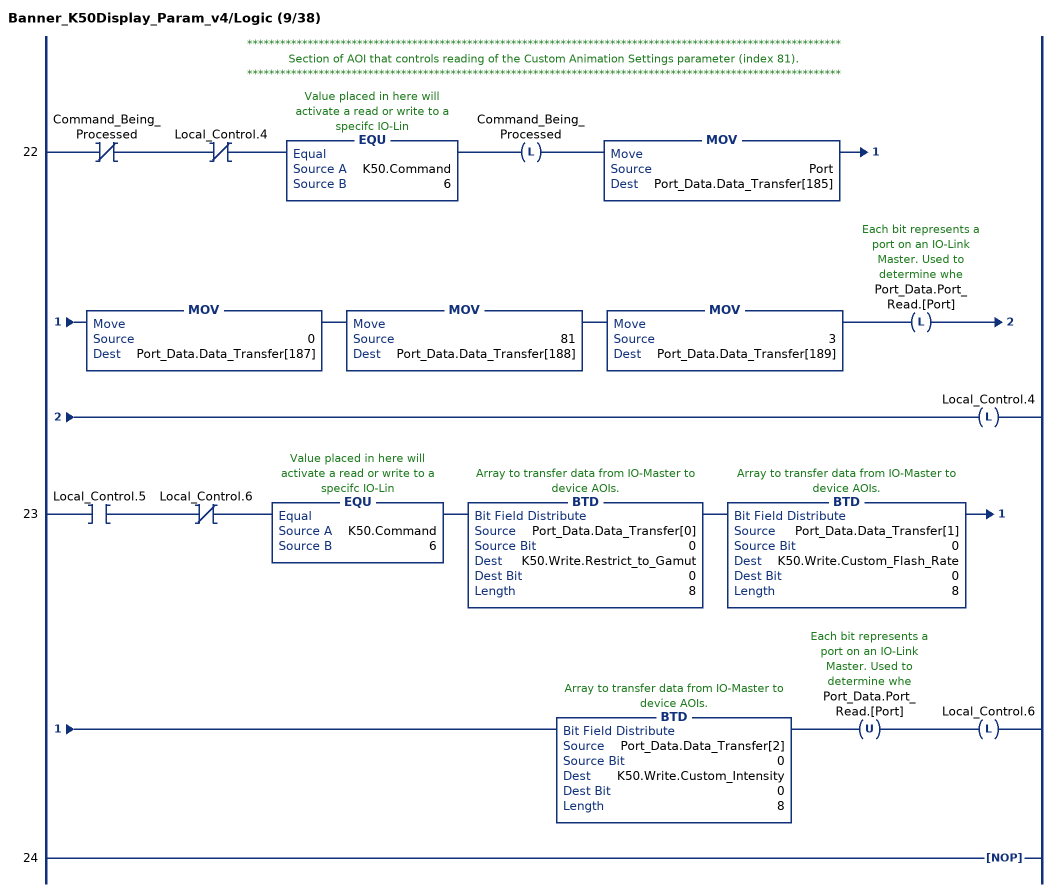
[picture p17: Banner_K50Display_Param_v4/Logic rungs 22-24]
   // ************************************************************************************************************
   // Section of AOI that controls reading of the Custom Animation Settings parameter (index 81).
   // ************************************************************************************************************
   22: XIO(Command_Being_Processed)XIO(Local_Control.4)EQU(K50.Command,6)OTL(Command_Being_Processed)MOV(Port,Port_Data.Data_Transfer[185])MOV(0,Port_Data.Data_Transfer[187])MOV(81,Port_Data.Data_Transfer[188])MOV(3,Port_Data.Data_Transfer[189])OTL(Port_Data.Port_Read.[Port])OTL(Local_Control.4);
   23: XIC(Local_Control.5)XIO(Local_Control.6)EQU(K50.Command,6)BTD(Port_Data.Data_Transfer[0],0,K50.Write.Restrict_to_Gamut,0,8)BTD(Port_Data.Data_Transfer[1],0,K50.Write.Custom_Flash_Rate,0,8)BTD(Port_Data.Data_Transfer[2],0,K50.Write.Custom_Intensity,0,8)OTU(Port_Data.Port_Read.[Port])OTL(Local_Control.6);
   24: NOP();
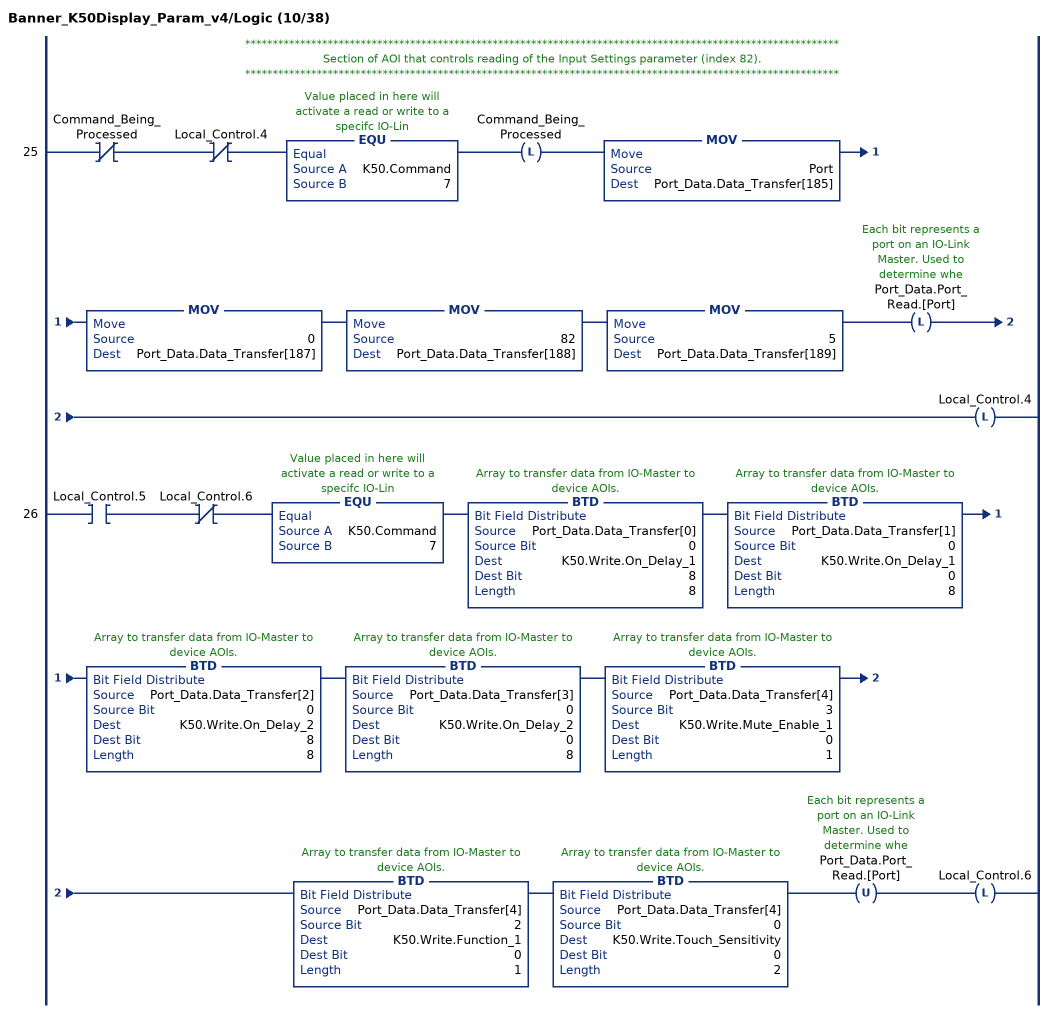
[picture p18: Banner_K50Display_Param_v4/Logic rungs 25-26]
   // ************************************************************************************************************
   // Section of AOI that controls reading of the Input Settings parameter (index 82).
   // ************************************************************************************************************
   25: XIO(Command_Being_Processed)XIO(Local_Control.4)EQU(K50.Command,7)OTL(Command_Being_Processed)MOV(Port,Port_Data.Data_Transfer[185])MOV(0,Port_Data.Data_Transfer[187])MOV(82,Port_Data.Data_Transfer[188])MOV(5,Port_Data.Data_Transfer[189])OTL(Port_Data.Port_Read.[Port])OTL(Local_Control.4);
   26: XIC(Local_Control.5)XIO(Local_Control.6)EQU(K50.Command,7)BTD(Port_Data.Data_Transfer[0],0,K50.Write.On_Delay_1,8,8)BTD(Port_Data.Data_Transfer[1],0,K50.Write.On_Delay_1,0,8)BTD(Port_Data.Data_Transfer[2],0,K50.Write.On_Delay_2,8,8)BTD(Port_Data.Data_Transfer[3],0,K50.Write.On_Delay_2,0,8)BTD(Port_Data.Data_Transfer[4],3,K50.Write.Mute_Enable_1,0,1)BTD(Port_Data.Data_Transfer[4],2,K50.Write.Function_1,0,1)BTD(Port_Data.Data_Transfer[4],0,K50.Write.Touch_Sensitivity,0,2)OTU(Port_Data.Port_Read.[Port])OTL(Local_Control.6);
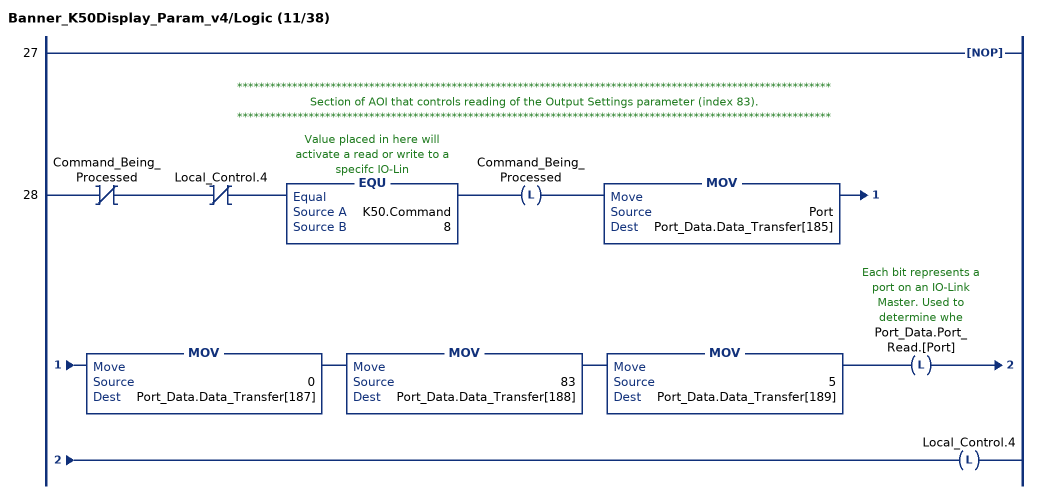
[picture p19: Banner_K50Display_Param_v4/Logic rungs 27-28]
   27: NOP();
   // ************************************************************************************************************
   // Section of AOI that controls reading of the Output Settings parameter (index 83).
   // ************************************************************************************************************
   28: XIO(Command_Being_Processed)XIO(Local_Control.4)EQU(K50.Command,8)OTL(Command_Being_Processed)MOV(Port,Port_Data.Data_Transfer[185])MOV(0,Port_Data.Data_Transfer[187])MOV(83,Port_Data.Data_Transfer[188])MOV(5,Port_Data.Data_Transfer[189])OTL(Port_Data.Port_Read.[Port])OTL(Local_Control.4);
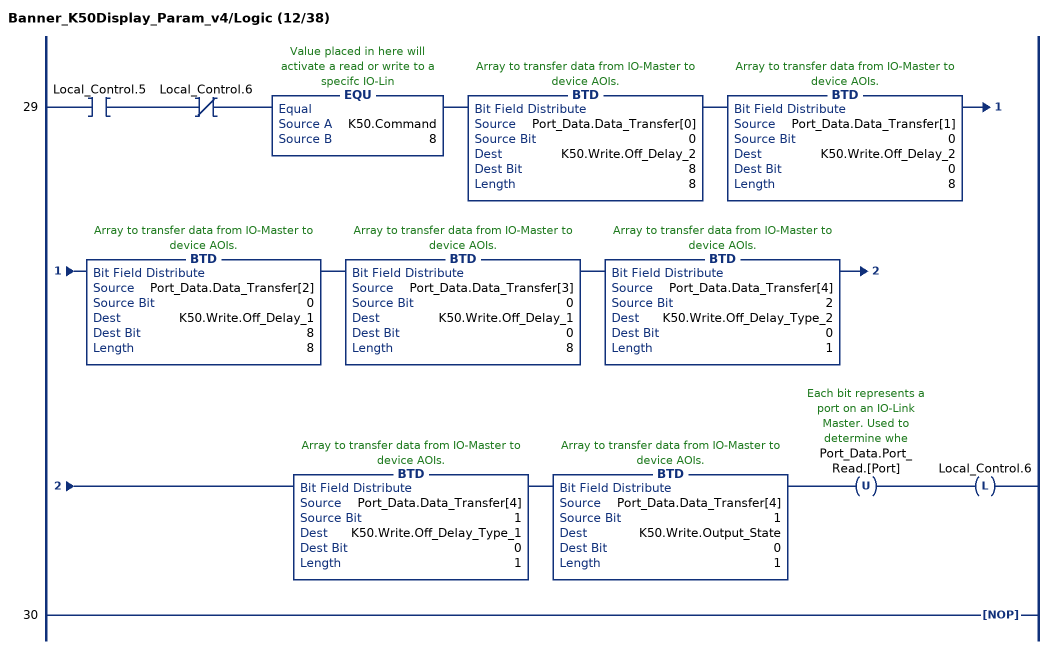
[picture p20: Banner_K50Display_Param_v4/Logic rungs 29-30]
   29: XIC(Local_Control.5)XIO(Local_Control.6)EQU(K50.Command,8)BTD(Port_Data.Data_Transfer[0],0,K50.Write.Off_Delay_2,8,8)BTD(Port_Data.Data_Transfer[1],0,K50.Write.Off_Delay_2,0,8)BTD(Port_Data.Data_Transfer[2],0,K50.Write.Off_Delay_1,8,8)BTD(Port_Data.Data_Transfer[3],0,K50.Write.Off_Delay_1,0,8)BTD(Port_Data.Data_Transfer[4],2,K50.Write.Off_Delay_Type_2,0,1)BTD(Port_Data.Data_Transfer[4],1,K50.Write.Off_Delay_Type_1,0,1)BTD(Port_Data.Data_Transfer[4],1,K50.Write.Output_State,0,1)OTU(Port_Data.Port_Read.[Port])OTL(Local_Control.6);
   30: NOP();
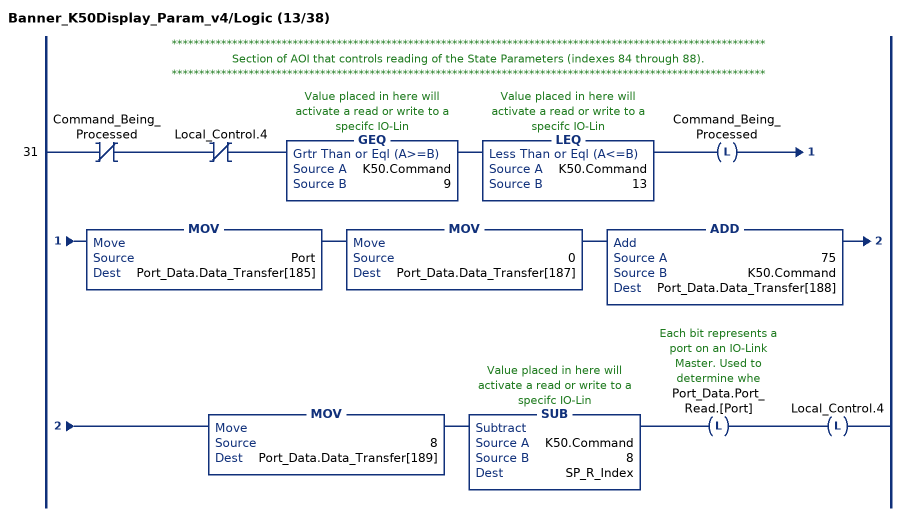
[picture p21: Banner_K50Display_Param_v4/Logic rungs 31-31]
   // ************************************************************************************************************
   // Section of AOI that controls reading of the State Parameters (indexes 84 through 88).
   // ************************************************************************************************************
   31: XIO(Command_Being_Processed)XIO(Local_Control.4)GEQ(K50.Command,9)LEQ(K50.Command,13)OTL(Command_Being_Processed)MOV(Port,Port_Data.Data_Transfer[185])MOV(0,Port_Data.Data_Transfer[187])ADD(75,K50.Command,Port_Data.Data_Transfer[188])MOV(8,Port_Data.Data_Transfer[189])SUB(K50.Command,8,SP_R_Index)OTL(Port_Data.Port_Read.[Port])OTL(Local_Control.4);
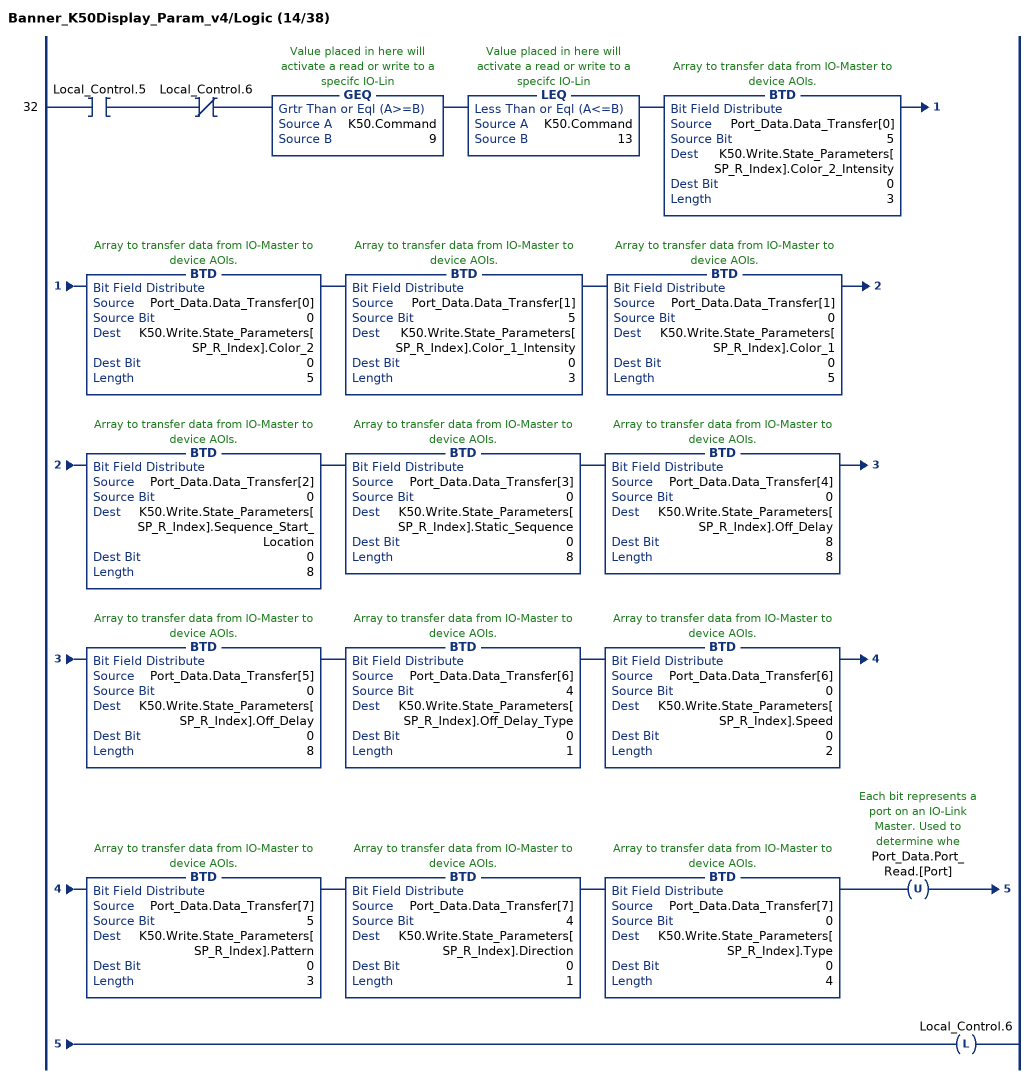
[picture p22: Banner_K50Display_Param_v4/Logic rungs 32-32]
   32: XIC(Local_Control.5)XIO(Local_Control.6)GEQ(K50.Command,9)LEQ(K50.Command,13)BTD(Port_Data.Data_Transfer[0],5,K50.Write.State_Parameters[SP_R_Index].Color_2_Intensity,0,3)BTD(Port_Data.Data_Transfer[0],0,K50.Write.State_Parameters[SP_R_Index].Color_2,0,5)BTD(Port_Data.Data_Transfer[1],5,K50.Write.State_Parameters[SP_R_Index].Color_1_Intensity,0,3)BTD(Port_Data.Data_Transfer[1],0,K50.Write.State_Parameters[SP_R_Index].Color_1,0,5)BTD(Port_Data.Data_Transfer[2],0,K50.Write.State_Parameters[SP_R_Index].Sequence_Start_Location,0,8)BTD(Port_Data.Data_Transfer[3],0,K50.Write.State_Parameters[SP_R_Index].Static_Sequence,0,8)BTD(Port_Data.Data_Transfer[4],0,K50.Write.State_Parameters[SP_R_Index].Off_Delay,8,8)BTD(Port_Data.Data_Transfer[5],0,K50.Write.State_Parameters[SP_R_Index].Off_Delay,0,8)BTD(Port_Data.Data_Transfer[6],4,K50.Write.State_Parameters[SP_R_Index].Off_Delay_Type,0,1)BTD(Port_Data.Data_Transfer[6],0,K50.Write.State_Parameters[SP_R_Index].Speed,0,2)BTD(Port_Data.Data_Transfer[7],5,K50.Write.State_Parameters[SP_R_Index].Pattern,0,3)BTD(Port_Data.Data_Transfer[7],4,K50.Write.State_Parameters[SP_R_Index].Direction,0,1)BTD(Port_Data.Data_Transfer[7],0,K50.Write.State_Parameters[SP_R_Index].Type,0,4)OTU(Port_Data.Port_Read.[Port])OTL(Local_Control.6);
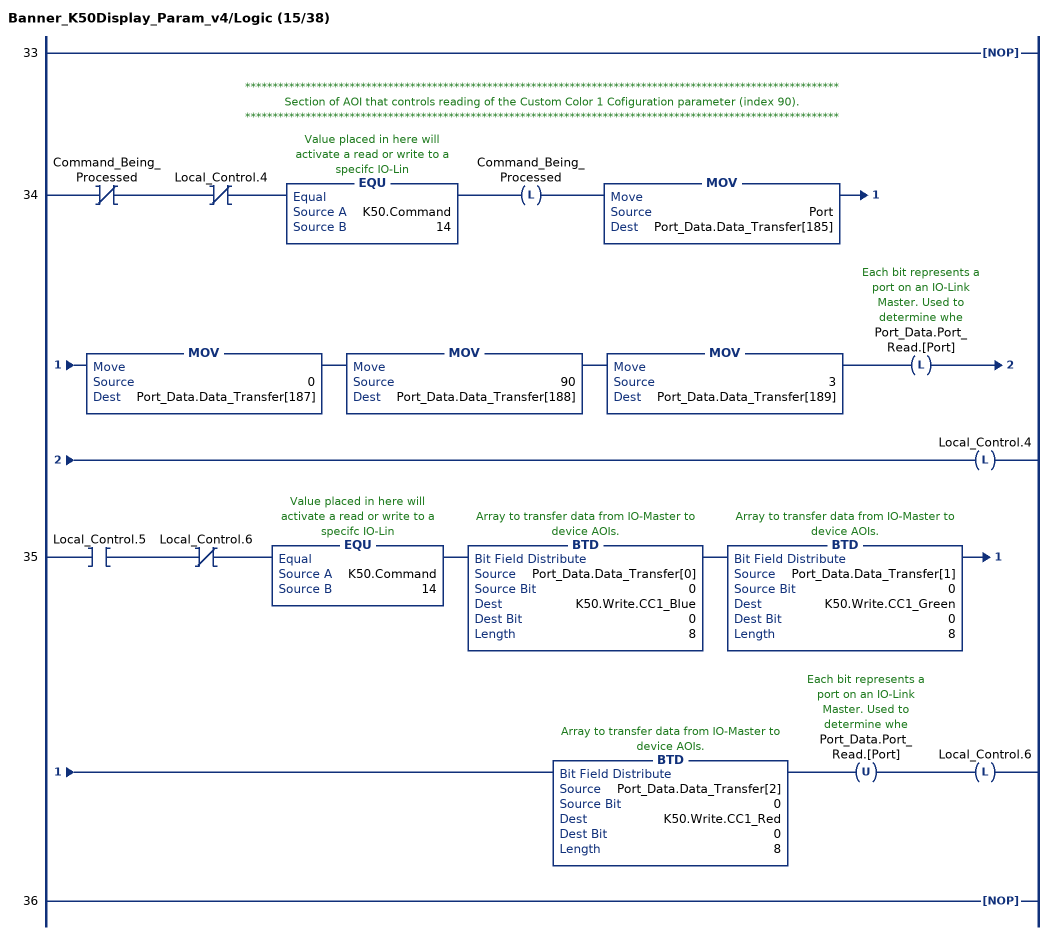
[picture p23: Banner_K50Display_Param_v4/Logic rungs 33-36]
   33: NOP();
   // ************************************************************************************************************
   // Section of AOI that controls reading of the Custom Color 1 Cofiguration parameter (index 90).
   // ************************************************************************************************************
   34: XIO(Command_Being_Processed)XIO(Local_Control.4)EQU(K50.Command,14)OTL(Command_Being_Processed)MOV(Port,Port_Data.Data_Transfer[185])MOV(0,Port_Data.Data_Transfer[187])MOV(90,Port_Data.Data_Transfer[188])MOV(3,Port_Data.Data_Transfer[189])OTL(Port_Data.Port_Read.[Port])OTL(Local_Control.4);
   35: XIC(Local_Control.5)XIO(Local_Control.6)EQU(K50.Command,14)BTD(Port_Data.Data_Transfer[0],0,K50.Write.CC1_Blue,0,8)BTD(Port_Data.Data_Transfer[1],0,K50.Write.CC1_Green,0,8)BTD(Port_Data.Data_Transfer[2],0,K50.Write.CC1_Red,0,8)OTU(Port_Data.Port_Read.[Port])OTL(Local_Control.6);
   36: NOP();
